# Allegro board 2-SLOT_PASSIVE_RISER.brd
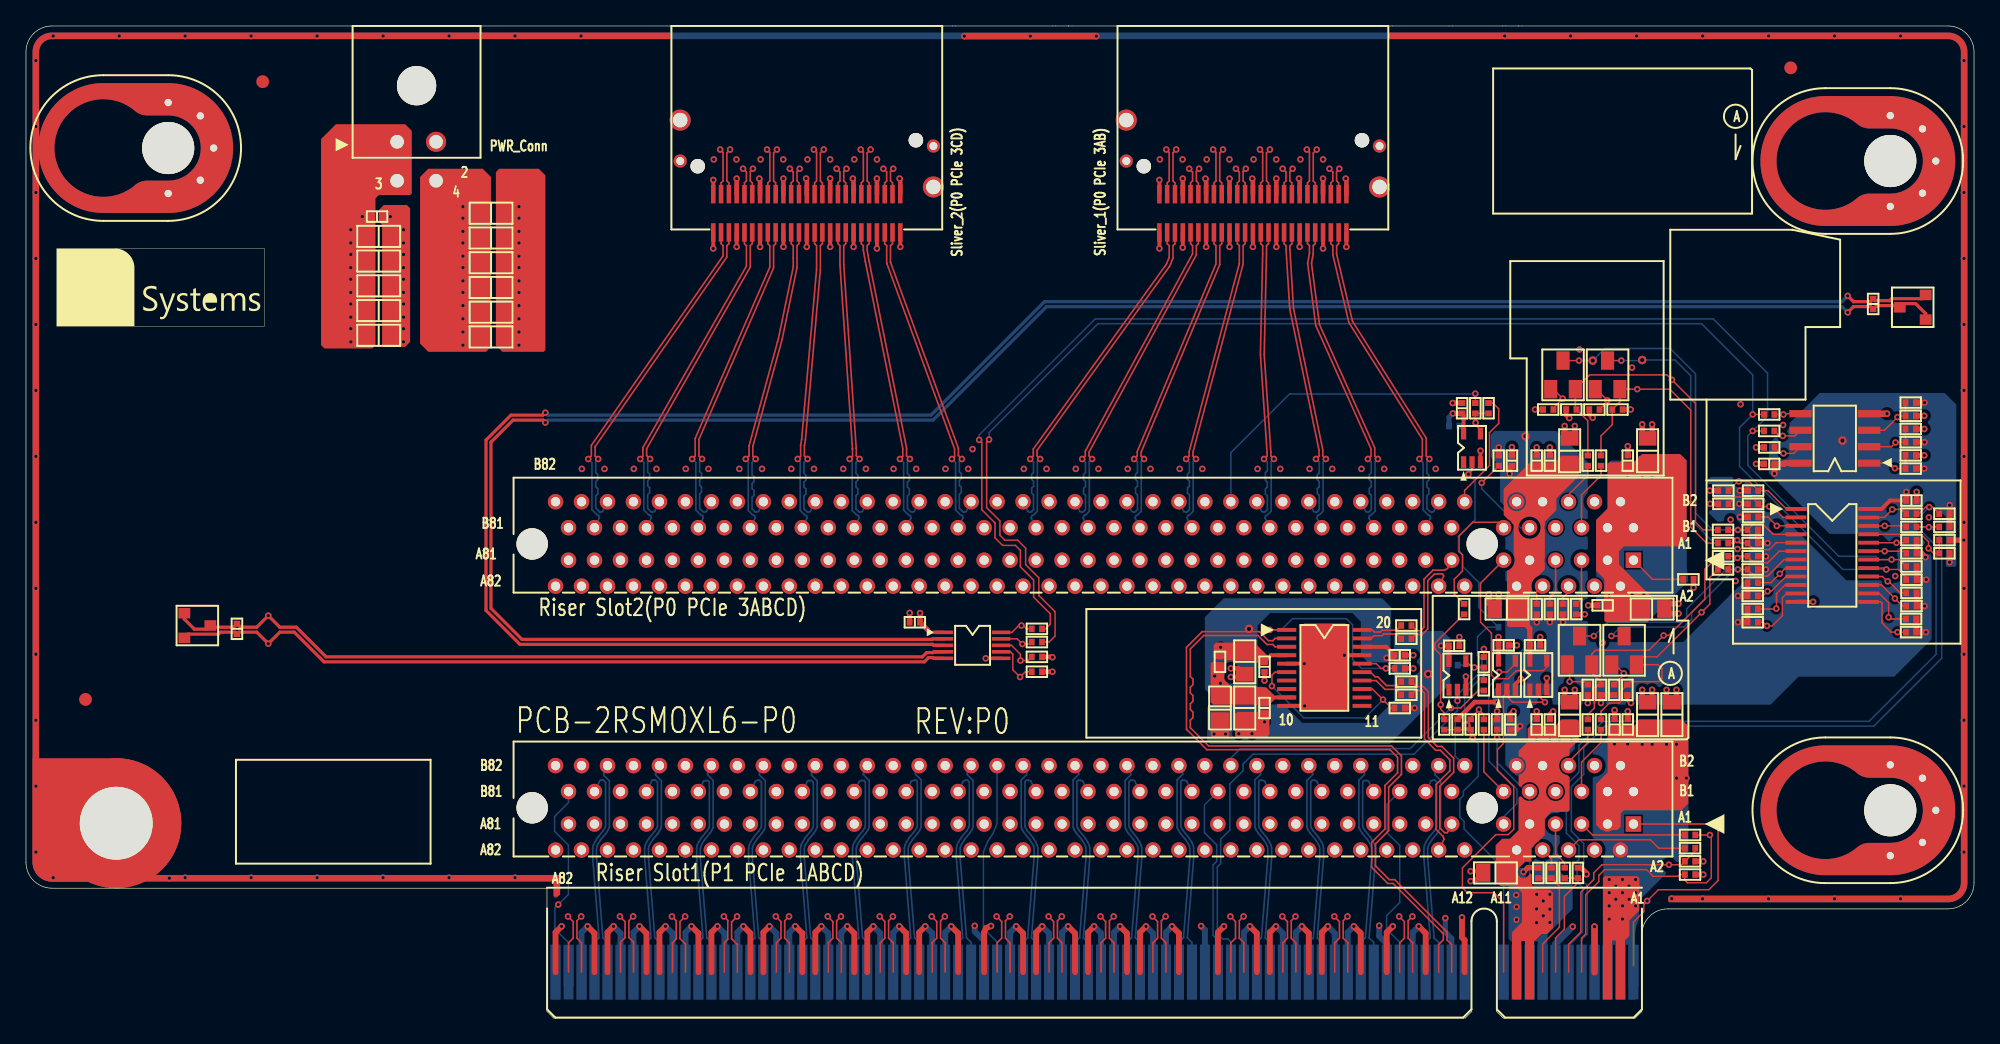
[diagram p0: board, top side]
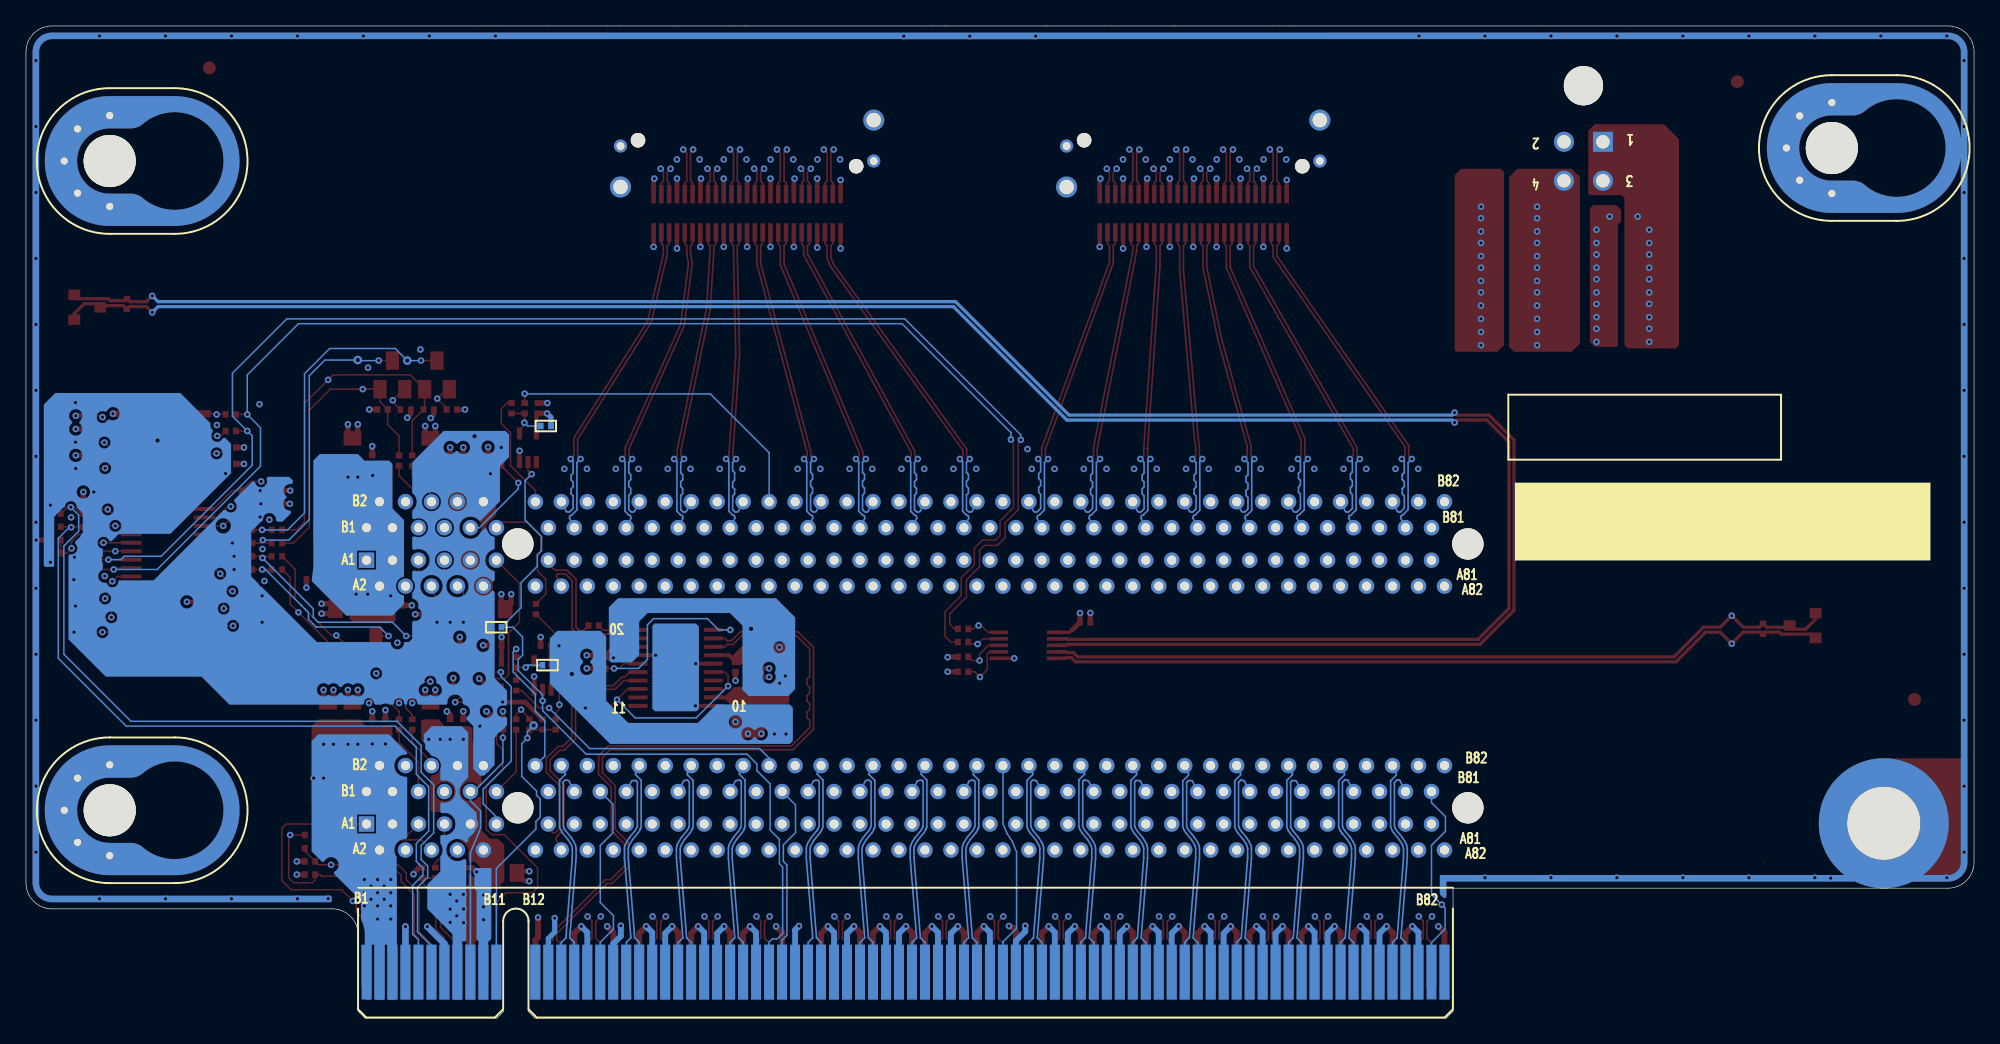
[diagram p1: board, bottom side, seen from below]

Outline 150 x 76.4 mm; copper layers: TOP, GND, IN1, IN2, GND1, BOTTOM. Coordinates in mm from the lower left corner of the outline.
Outline path: 0,74.4 arc(0.59,75.81) 2,76.4 148,76.4 arc(149.41,75.81) 150,74.4 150,10.41 arc(149.41,8.99) 148,8.41 126.42,8.41 arc(125,7.82) 124.42,6.41 124.42,0.51 123.91,0 113.74,0 113.23,0.51 113.23,7.45 arc(112.28,8.41) 111.32,7.45 111.32,0.51 110.82,0 40.62,0 40.12,0.51 40.12,10 2,10 arc(0.59,10.59) 0,12 0,74.4

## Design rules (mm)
constraint set DEFAULT: min track width 0.117
net group CLK_100M_SLOT1_R_DN: nets CLK_100M_SLOT2_DN CLK_100M_SLOT2_R_DN
net group CLK_100M_SLOT1_R_DP: nets CLK_100M_SLOT2_DP CLK_100M_SLOT2_R_DP
net group CLK_100M_SLOT2_R_DN: nets CLK_100M_SLOT1_DN CLK_100M_SLOT1_R_DN
net group CLK_100M_SLOT2_R_DP: nets CLK_100M_SLOT1_DP CLK_100M_SLOT1_R_DP
net group I2C_MB_RISER_SDA: nets I2C_MB_RISER_SDA I2C_PCA9548_SDA
net group I2C_PCA9548_SCL: nets I2C_MB_RISER_SCL I2C_PCA9548_SCL
net group I2C_EMC1413_SCL: nets I2C_BUF_CH6_SCL I2C_EMC1413_SCL I2C_FRU_SCL
net group I2C_FRU_SDA: nets I2C_BUF_CH6_SDA I2C_EMC1413_SDA I2C_FRU_SDA
net group I2C_SLOT1_SCL: nets I2C_BUF_SLOT1_SCL I2C_SLOT1_R_SCL I2C_SLOT1_SCL
net group I2C_SLOT1_SDA: nets I2C_BUF_SLOT1_SDA I2C_SLOT1_R_SDA I2C_SLOT1_SDA
net group I2C_SLOT2_SCL: nets I2C_BUF_SLOT2_SCL I2C_SLOT2_R_SCL I2C_SLOT2_SCL
net group I2C_SLOT2_SDA: nets I2C_BUF_SLOT2_SDA I2C_SLOT2_R_SDA I2C_SLOT2_SDA

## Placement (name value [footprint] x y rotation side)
C1  -  [C0805]  124.86 43.69 90 top
C2  -  [C0805]  114.03 31.5 180 top
C3  -  [C0402]  123.34 42.93 90 top
C4  -  [C0402]  117.34 42.93 90 top
C5  -  [C0402]  121.4 31.78 180 top
C6  -  [C0402]  116.32 42.93 90 top
C7  -  [C0402]  114.42 42.93 90 top
C8  -  [C0805]  124.86 23.37 90 top
C9  -  [C0805]  118.86 23.37 90 top
C10  -  [C0402]  123.34 22.61 90 top
C11  -  [C0402]  117.34 22.61 90 top
C12  -  [C0402]  122.32 22.61 90 top
C13  -  [C0402]  116.32 22.61 90 top
C14  -  [C0402]  114.29 22.61 90 top
C15  -  [C0805]  93.84 27.43 270 top
C16  -  [C0402]  95.37 27.05 270 top
C17  -  [C0805]  93.84 23.88 270 top
C18  -  [C0402]  105.78 27.94 0 top
C19  -  [C0402]  95.37 23.88 270 top
C20  -  [C0402]  145.18 39.85 0 top
C21  -  [C0402]  68.44 30.48 180 top
C22  -  [C0402]  134.23 42.67 180 top
C23  -  [C0402]  16.24 29.97 270 top
C24  -  [C0402]  142.23 54.99 90 top
C25  -  [C0402]  110.58 46.96 90 top
C26  -  [C0402]  116.19 28.7 0 top
C27  -  [C0402]  113.78 28.7 0 top
C28  -  [C0402]  109.97 28.67 0 top
C29  -  [C0402]  27.03 61.72 180 top
C30  -  [C0805]  27.16 52.58 180 top
C31  -  [C0805]  27.16 54.48 180 top
C32  -  [C0805]  125.21 31.5 0 top
C33  -  [C0805]  118.86 43.69 90 top
C34  -  [C0805]  126.73 23.37 90 top
C35  -  [C0805]  113.15 11.18 180 top
C36  -  [C0805]  35.81 60.07 0 top
C37  -  [C0805]  35.81 56.26 0 top
C38  -  [C0805]  35.81 54.36 0 top
C39  -  [C0805]  27.16 56.39 180 top
C40  -  [C0805]  35.81 61.98 0 top
C41  -  [C0805]  27.16 60.2 180 top
C42  -  [C0805]  35.81 52.45 0 top
C43  -  [C0805]  27.16 58.29 180 top
C44  -  [C0805]  35.81 58.17 0 top
J1  -  [PCIE_X16D_H11]  123.78 14.94 270 top
J2  -  [PCIE_X16D_H11]  123.78 35.26 270 top
J3  -  [GF_PCIE_X16]  112.28 7.45 180 bottom
J4  -  [SLIVER_X8_RA]  94.45 68.57 180 top
J5  -  [SLIVER_X8_RA]  60.1 68.57 180 top
J6  -  [PWR2X2D1NH_P3W3H8-9_RA]  28.57 67.48 180 top
L1  -  [B2012]  91.94 23.88 90 top
ME1  -  [ZT_LOG_6X16]  2.35 53.26 0 top
ME2  -  [LABEL_32X6_FULL]  35.36 35.23 180 bottom
ME3  -  [LABEL20X4_SST21X5]  35.86 43 180 bottom
MH1  -  [HOLE_C10D5-6B10_NPB_STANDOFF]  6.95 15 180 bottom
MH2  -  [GND_C10D4_6-5B10_OB5]  10.95 67 270 top
MH3  -  [GND_C10D4_6-5B10_OB5]  143.55 66 270 top
MH5  -  [GND_C10D4_6-5B10_OB5]  143.55 16 270 top
NOREF  -  []  61.05 66.88 0 top
NOREF#2  -  []  46.24 7.82 0 top
NOREF#3  -  []  70.24 7.82 0 top
NOREF#4  -  [unnamed#2]  18.23 72.11 0 top
NOREF#5  -  []  85.71 43.05 0 top
NOREF#6  -  []  62.8 65.41 0 top
NOREF#7  -  []  47.68 43.05 0 top
NOREF#8  -  []  103.71 43.05 0 top
NOREF#9  -  []  67.68 43.05 0 top
NOREF#10  -  []  95.4 66.88 0 top
NOREF#11  -  []  53.83 66.88 0 top
NOREF#12  -  []  42.24 7.82 0 top
NOREF#13  -  []  93.24 7.82 0 top
NOREF#14  -  [unnamed#2]  4.59 24.54 0 top
NOREF#15  -  []  95.71 43.05 0 top
NOREF#16  -  []  99.71 43.05 0 top
NOREF#17  -  []  63.8 43.05 0 top
NOREF#18  -  []  66.24 7.82 0 top
NOREF#19  -  []  58.24 7.82 0 top
NOREF#20  -  []  93.55 65.41 0 top
NOREF#21  -  []  81.71 43.05 0 top
NOREF#22  -  []  14.59 -76.5 0 top
NOREF#23  -  []  91.79 66.88 0 top
NOREF#24  -  []  88.18 66.88 0 top
NOREF#25  -  []  55.6 65.41 0 top
NOREF#26  -  []  64.65 66.88 0 top
NOREF#27  -  []  101.24 7.82 0 top
NOREF#28  -  []  62.24 7.82 0 top
NOREF#29  -  []  54.24 7.82 0 top
NOREF#30  -  []  99 66.88 0 top
NOREF#31  -  []  59.2 65.41 0 top
NOREF#32  -  []  97.15 65.41 0 top
NOREF#33  -  []  55.8 43.05 0 top
NOREF#34  -  []  87.24 7.82 0 top
NOREF#35  -  []  66.4 65.41 0 top
NOREF#36  -  []  75.24 7.82 0 top
NOREF#37  -  []  77.71 43.05 0 top
NOREF#38  -  []  50.24 7.82 0 top
NOREF#39  -  []  43.68 43.05 0 top
NOREF#40  -  []  57.44 66.88 0 top
NOREF#41  -  [unnamed#2]  135.88 73.18 0 top
NOREF#42  -  []  89.71 43.05 0 top
NOREF#43  -  []  51.68 43.05 0 top
NOREF#44  -  []  107.68 43.05 0 top
NOREF#45  -  []  83.24 7.82 0 top
NOREF#46  -  []  89.95 65.41 0 top
NOREF#47  -  []  71.68 43.05 0 top
NOREF#48  -  []  59.8 43.05 0 top
NOREF#49  -  []  106.24 7.82 0 top
NOREF#50  -  []  97.24 7.82 0 top
NOREF#51  -  [unnamed#2]  16.17 11.89 0 top
NOREF#52  -  []  100.75 65.41 0 top
NOREF#53  -  []  79.24 7.82 0 top
Q1  -  [SOT23_GDS]  118.35 49.53 90 top
Q2  -  [SOT23_GDS]  119.62 28.32 90 top
Q3  -  [SOT23_GDS]  121.78 49.53 90 top
Q4  -  [SOT23_GDS]  123.05 28.32 90 top
Q5  -  [SOT23]  13.2 30.23 0 top
Q6  -  [SOT23]  145.28 54.74 180 top
R1  -  [R0402]  121.27 42.93 270 top
R2  -  [R0402]  120.26 42.93 270 top
R3  -  [R0402]  110.73 31.5 90 top
R4  -  [R0402]  128 33.78 0 top
R5  -  [R0402]  128.13 12.06 180 top
R6  -  [R0402]  119.5 11.18 270 top
R7  -  [R0402]  116.45 11.18 270 top
R8  -  [R0402]  128.13 11.05 180 top
R9  -  [R0402]  121.27 22.61 270 top
R10  -  [R0402]  120.26 22.61 270 top
R11  -  [R0402]  112.26 22.61 270 top
R12  -  [R0402]  130.7 40.62 180 top
R13  -  [R0402]  132.99 39.6 0 top
R14  -  [R0402]  130.7 39.6 180 top
R15  -  [R0402]  91.94 27.43 90 top
R16  -  [R0402]  147.72 36.81 0 top
R17  -  [R0402]  145.18 38.84 180 top
R18  -  [R0402]  105.78 26.92 180 top
R19  -  [R0402]  105.78 23.88 180 top
R20  -  [R0402]  132.96 37.59 180 top
R21  -  [R0402]  132.96 36.58 180 top
R22  -  [R0402]  132.96 35.56 180 top
R23  -  [R0402]  132.96 34.54 180 top
R24  -  [R0402]  132.96 33.53 0 top
R25  -  [R0402]  132.96 32.51 0 top
R26  -  [R0402]  147.72 38.84 180 top
R27  -  [R0402]  147.72 37.82 180 top
R28  -  [R0402]  106.29 30.23 0 top
R29  -  [R0402]  106.29 29.21 0 top
R30  -  [R0402]  106.29 25.91 0 top
R31  -  [R0402]  106.29 24.89 0 top
R32  -  [R0402]  117.21 46.86 0 top
R33  -  [R0402]  120.26 25.27 90 top
R34  -  [R0402]  120.77 46.86 0 top
R35  -  [R0402]  122.29 25.27 90 top
R36  -  [R0402]  118.99 46.86 0 top
R37  -  [R0402]  121.27 25.27 90 top
R38  -  [R0402]  122.54 46.86 180 top
R39  -  [R0402]  123.31 25.27 90 top
R40  -  [R0402]  134.23 46.48 0 top
R41  -  [R0402]  77.84 28.96 180 top
R42  -  [R0402]  134.23 43.94 180 top
R43  -  [R0402]  145.12 43.33 0 top
R44  -  [R0402]  145.12 44.35 180 top
R45  -  [R0402]  145.12 45.36 0 top
R46  -  [R0402]  145.12 47.39 180 top
R47  -  [R0402]  145.12 46.38 0 top
R48  -  [R0402]  109.21 22.61 270 top
R49  -  [R0402]  111.24 22.61 270 top
R50  -  [R0402]  113.27 22.61 270 top
R51  -  [R0402]  128.13 14.1 0 top
R52  -  [R0402]  128.13 13.08 0 top
R53  -  [R0402]  118.48 11.18 270 top
R54  -  [R0402]  117.46 11.18 270 top
R55  -  [R0402]  132.99 40.62 0 top
R56  -  [R0402]  147.72 35.79 180 top
R57  -  [R0402]  145.18 37.82 180 top
R58  -  [R0402]  134.23 45.21 0 top
R59  -  [R0402]  77.84 29.97 180 top
R60  -  [R0402]  145.12 42.31 180 top
R61  -  [R0402]  110.22 22.61 270 top
R62  -  [R0402]  132.99 38.58 0 top
R63  -  [R0402]  132.96 31.5 0 top
R64  -  [R0402]  132.96 30.48 0 top
R65  -  [R0402]  145.15 29.72 180 top
R66  -  [R0402]  145.15 30.73 180 top
R67  -  [R0402]  145.18 31.73 180 top
R68  -  [R0402]  145.18 32.74 180 top
R69  -  [R0402]  145.18 33.76 180 top
R70  -  [R0402]  145.18 34.77 180 top
R71  -  [R0402]  145.18 35.79 180 top
R72  -  [R0402]  145.18 36.81 180 top
R73  -  [R0402]  112.61 46.96 90 top
R74  -  [R0402]  111.6 46.96 90 top
R75  -  [R0402]  112.25 27.4 90 top
R76  -  [R0402]  112.25 25.62 270 top
R77  -  [R0402]  113.4 42.93 270 top
R78  -  [R0402]  118.35 31.5 90 top
R79  -  [R0402]  117.34 31.5 90 top
R80  -  [R0402]  116.32 31.5 90 top
R81  -  [R0402]  119.37 31.5 90 top
R82  -  [R0402]  130.67 36.58 180 top
R83  -  [R0402]  130.67 34.54 180 top
R84  -  [R0402]  130.67 37.59 180 top
R85  -  [R0402]  130.67 35.56 180 top
R86  -  [R0402]  77.84 27.81 180 top
R87  -  [R0402]  77.84 26.67 180 top
R88  -  [R0402]  113.78 30.1 180 bottom
R89  -  [R0402]  109.97 45.59 0 bottom
R90  -  [R0402]  109.84 27.18 0 bottom
U1  -  [TSSOP24_P0-65W5-6H1-2]  139.08 35.63 0 top
U2  -  [MSOP10_P0-5W4-4_3X3]  72.89 28.7 0 top
U3  -  [SOIC8]  139.28 44.64 180 top
U4  -  [SC70-5XB]  116.45 26.42 90 top
U5  -  [SC70-5XB]  111.34 43.91 90 top
U6  -  [SC70-5XB]  114.03 26.42 90 top
U7  -  [SC70-5XB]  110.22 26.38 90 top
U8  -  [TSSOP20_P0-65W5-8H1-2]  99.97 26.96 0 top

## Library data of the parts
C1 C2 C8 C9 C15 C17 = CAP: part number: CAP_0805-10UF,CAP-85E00010-D0,X6S,10%,16V
C3-C7 C10-C14 C16 C18-C22 C25-C29 = CAP: part number: CAP_0402-0.1UF,CAP-42E000D1-D0,X7R,10%,16V
C23 C24 = CAP: part number: CAP_0402-2200PF,CAP-42GD0022-D0,X7R,10%,50V
C30-C44 = CAP: part number: CAP_0805-22UF,CAP-85E00022-E0,X6S,20%,16V
J1 J2 = PCIE_X16: part number: PCIE_X16_-2EG08213-9ADM-JF,COB-PCE164DV-03,IO,,
J3 = GF_PCIE_X16: part number: GF_PCIE_X16_-GF_PCIE_X16,,,,
J4 J5 = SLIVER_X8_50P: part number: SLIVER_X8_50P_-2292055-1,COS-SLV050SR-00,IO,,
J6 = PWR2X2: part number: PWR2X2_-1NH_PWR2X2,COP-004D0003-01,IO,,,
L1 = BEAD: part number: BEAD_-600,BED-06002012-00,IC,25%,,
ME1 = DUMMY_SYMBOL_NO_PIN: part number: DUMMY_SYMBOL_NO_PIN_-ZT_LOG_6X16,MEDUMMY3,EMPTY,,
ME2 = DUMMY_SYMBOL_NO_PIN: part number: DUMMY_SYMBOL_NO_PIN_-LABEL_32X6_FULL,MEDUMMY7,EMPTY,,
ME3 = DUMMY_SYMBOL_NO_PIN: part number: DUMMY_SYMBOL_NO_PIN_-LABEL20X4_SST21X5,MEDUMMY5,EMPTY,,
MH1 = STANDOFF: part number: STANDOFF_-HOLE_C10D5-6B10_NPB_STANDOFF,TSW-AM3L5P1P-00,IO,,
MH2 MH3 MH5 = SCREW_NP_5VIA: part number: SCREW_NP_5VIA_-C10D4XC10D6.5_5V,TEMP_C10D4XC10D6.5_L5,EMPTY,,
Q1 Q3 = 2N7002: part number: 2N7002_-2N7002,MOS-002N7002-00,EMPTY,,,; signal model: 2N7002_-2N7002_MOS-002N7002-00A
Q2 Q4 = 2N7002: part number: 2N7002_-2N7002,MOS-002N7002-00,IC,,,; signal model: 2N7002_-2N7002_MOS-002N7002-00A
Q5 Q6 = NPN: part number: NPN_-MMBT3904LT1G,BJT-MMBT3904-00,IC,,,
R1 R2 R9 R10 R40 R41 R58 R59 R82 R84 = RES: part number: RES_0402-0,RES-42000000-C0,IC,5%,1A; signal model: R0402
R3 R11 R15 R48 R49 R51-R54 R74 R76 = RES: part number: RES_0402-0,RES-42000000-C0,IC,5%,1A
R4 R89 R90 = RES: part number: RES_0402-10K,RES-4200010K-B0,IC,1%,1/16W
R5-R8 R55 R56 R60 R61 R77-R81 = RES: part number: RES_0402-4.7K,RES-42004D7K-B0,EMPTY,1%,1/16W
R12 R16 R18 R32-R35 R42 R43 = RES: part number: RES_0402-100,RES-42000100-B0,IC,1%,1/16W
R13 R19 R24 R25 R44 R46 R62-R68 R71 R72 R86 R87 = RES: part number: RES_0402-4.7K,RES-42004D7K-B0,IC,1%,1/16W
R14 R45 R47 = RES: part number: RES_0402-100,RES-42000100-B0,EMPTY,1%,1/16W
R17 R57 = RES: part number: RES_0402-22,RES-42000022-B0,IC,1%,1/16W; signal model: R0402
R20-R23 R37 R39 R69 R70 = RES: part number: RES_0402-4.7K,RES-42004D7K-B0,IC,1%,1/16W; signal model: R0402
R26 R27 R36 R38 = RES: part number: RES_0402-4.7K,RES-42004D7K-B0,EMPTY,1%,1/16W; signal model: R0402
R28-R31 = RES: part number: RES_0402-27.4,RES-420027D4-B0,IC,1%,1/16W; signal model: R0402
R50 R88 = RES: part number: RES_0402-10K,RES-4200010K-B0,EMPTY,1%,1/16W
R73 R75 = RES: part number: RES_0402-0,RES-42000000-C0,EMPTY,5%,1A
R83 R85 = RES: part number: RES_0402-0,RES-42000000-C0,EMPTY,5%,1A; signal model: R0402
U1 = PCA9548: part number: PCA9548_-PCA9548APW,ICC-PCA9548A-00,IC,,
U2 = EMC1413AAIZLTR: part number: EMC1413AAIZLTR_-EMC1413-A-AIZL-TR,ICC-EMC1413A-00,IC,,
U3 = AT24C64D: part number: AT24C64D_-AT24C64D-SSHM-T,ICM-AT24C64D-00,IC,,
U4 U6 = SN74LVC1G17: part number: SN74LVC1G17_-SN74LVC1G17DCKR,ICC-LVC1G17D-00,IC,,,
U5 U7 = SN74LVC1G07: part number: SN74LVC1G07_-SN74LVC1G07DCKR,ICC-LVC1G07D-00,IC,,,
U8 = 9DBL411B: part number: 9DBL411B_-9DBL411BGILFT,ICC-9DBL411B-00,IC,,

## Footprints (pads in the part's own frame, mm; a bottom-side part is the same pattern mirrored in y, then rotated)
B2012
  rect 1.118x1.372 smd: 1(-0.95,0) 2(0.95,0)
C0402
  rect 0.457x0.508 smd: 1(-0.4,0) 2(0.4,0)
C0805
  rect 1.118x1.372 smd: 1(-0.95,0) 2(0.95,0)
GF_PCIE_X16
  rect 0.762x3.2 smd: A1(-11.5,-3.42) B81(70.5,-3.42)
  rect 0.762x4.216 smd: A2(-10.5,-3.92) A3(-9.5,-3.92) A4(-8.5,-3.92) A5(-7.5,-3.92) A6(-6.5,-3.92) A7(-5.5,-3.92) A8(-4.5,-3.92) A9(-3.5,-3.92) A10(-2.5,-3.92) A11(-1.5,-3.92) A12(1.5,-3.92) A13(2.5,-3.92) A14(3.5,-3.92) A15(4.5,-3.92) A16(5.5,-3.92) A17(6.5,-3.92) A18(7.5,-3.92) A19(8.5,-3.92) A20(9.5,-3.92) A21(10.5,-3.92) A22(11.5,-3.92) A23(12.5,-3.92) A24(13.5,-3.92) A25(14.5,-3.92) A26(15.5,-3.92) A27(16.5,-3.92) A28(17.5,-3.92) A29(18.5,-3.92) A30(19.5,-3.92) A31(20.5,-3.92) A32(21.5,-3.92) A33(22.5,-3.92) A34(23.5,-3.92) A35(24.5,-3.92) A36(25.5,-3.92) A37(26.5,-3.92) A38(27.5,-3.92) A39(28.5,-3.92) A40(29.5,-3.92) A41(30.5,-3.92) A42(31.5,-3.92) A43(32.5,-3.92) A44(33.5,-3.92) A45(34.5,-3.92) A46(35.5,-3.92) A47(36.5,-3.92) A48(37.5,-3.92) A49(38.5,-3.92) A50(39.5,-3.92) A51(40.5,-3.92) A52(41.5,-3.92) A53(42.5,-3.92) A54(43.5,-3.92) A55(44.5,-3.92) A56(45.5,-3.92) A57(46.5,-3.92) A58(47.5,-3.92) A59(48.5,-3.92) A60(49.5,-3.92) A61(50.5,-3.92) A62(51.5,-3.92) A63(52.5,-3.92) A64(53.5,-3.92) A65(54.5,-3.92) A66(55.5,-3.92) A67(56.5,-3.92) A68(57.5,-3.92) A69(58.5,-3.92) A70(59.5,-3.92) A71(60.5,-3.92) A72(61.5,-3.92) A73(62.5,-3.92) A74(63.5,-3.92) A75(64.5,-3.92) A76(65.5,-3.92) A77(66.5,-3.92) A78(67.5,-3.92) A79(68.5,-3.92) A80(69.5,-3.92) A81(70.5,-3.92) A82(71.5,-3.92) B1(-11.5,-3.92) B2(-10.5,-3.92) B3(-9.5,-3.92) B4(-8.5,-3.92) B5(-7.5,-3.92) B6(-6.5,-3.92) B7(-5.5,-3.92) B8(-4.5,-3.92) B9(-3.5,-3.92) B10(-2.5,-3.92) B11(-1.5,-3.92) B12(1.5,-3.92) B13(2.5,-3.92) B14(3.5,-3.92) B15(4.5,-3.92) B16(5.5,-3.92) B17(6.5,-3.92) B18(7.5,-3.92) B19(8.5,-3.92) B20(9.5,-3.92) B21(10.5,-3.92) B22(11.5,-3.92) B23(12.5,-3.92) B24(13.5,-3.92) B25(14.5,-3.92) B26(15.5,-3.92) B27(16.5,-3.92) B28(17.5,-3.92) B29(18.5,-3.92) B30(19.5,-3.92) B31(20.5,-3.92) B32(21.5,-3.92) B33(22.5,-3.92) B34(23.5,-3.92) B35(24.5,-3.92) B36(25.5,-3.92) B37(26.5,-3.92) B38(27.5,-3.92) B39(28.5,-3.92) B40(29.5,-3.92) B41(30.5,-3.92) B42(31.5,-3.92) B43(32.5,-3.92) B44(33.5,-3.92) B45(34.5,-3.92) B46(35.5,-3.92) B47(36.5,-3.92) B48(37.5,-3.92) B49(38.5,-3.92) B50(39.5,-3.92) B51(40.5,-3.92) B52(41.5,-3.92) B53(42.5,-3.92) B54(43.5,-3.92) B55(44.5,-3.92) B56(45.5,-3.92) B57(46.5,-3.92) B58(47.5,-3.92) B59(48.5,-3.92) B60(49.5,-3.92) B61(50.5,-3.92) B62(51.5,-3.92) B63(52.5,-3.92) B64(53.5,-3.92) B65(54.5,-3.92) B66(55.5,-3.92) B67(56.5,-3.92) B68(57.5,-3.92) B69(58.5,-3.92) B70(59.5,-3.92) B71(60.5,-3.92) B72(61.5,-3.92) B73(62.5,-3.92) B74(63.5,-3.92) B75(64.5,-3.92) B76(65.5,-3.92) B77(66.5,-3.92) B78(67.5,-3.92) B79(68.5,-3.92) B80(69.5,-3.92) B82(71.5,-3.92)
GND_C10D4_6-5B10_OB5
  round 4.013 hole 4.013 unplated: (0,0)
  round 0.762 hole 0.559: 2(-3.5,0) 3(-2.475,2.475) 4(0,3.5) 5(2.475,2.475) 6(3.5,0)
HOLE_C10D5-6B10_NPB_STANDOFF
  round 10.008 hole 5.613: 1(0,0)
MSOP10_P0-5W4-4_3X3
  rect 1.422x0.279 smd: 1(-2.2,1) 2(-2.2,0.5) 3(-2.2,0) 4(-2.2,-0.5) 5(-2.2,-1) 6(2.2,-1) 7(2.2,-0.5) 8(2.2,0) 9(2.2,0.5) 10(2.2,1)
PCIE_X16D_H11
  round 2.413 hole 2.413 unplated: (-1.25,-11.65) (-1.25,-84.8)
  rect 1.194x1.194 hole 0.711: A1(0,0)
  round 1.194 hole 0.711: A2(2,-1) A3(0,-2) A4(2,-3) A5(0,-4) A6(2,-5) A7(0,-6) A8(2,-7) A9(0,-8) A10(2,-9) A11(0,-10) A12(2,-13) A13(0,-14) A14(2,-15) A15(0,-16) A16(2,-17) A17(0,-18) A18(2,-19) A19(0,-20) A20(2,-21) A21(0,-22) A22(2,-23) A23(0,-24) A24(2,-25) A25(0,-26) A26(2,-27) A27(0,-28) A28(2,-29) A29(0,-30) A30(2,-31) A31(0,-32) A32(2,-33) A33(0,-34) A34(2,-35) A35(0,-36) A36(2,-37) A37(0,-38) A38(2,-39) A39(0,-40) A40(2,-41) A41(0,-42) A42(2,-43) A43(0,-44) A44(2,-45) A45(0,-46) A46(2,-47) A47(0,-48) A48(2,-49) A49(0,-50) A50(2,-51) A51(0,-52) A52(2,-53) A53(0,-54) A54(2,-55) A55(0,-56) A56(2,-57) A57(0,-58) A58(2,-59) A59(0,-60) A60(2,-61) A61(0,-62) A62(2,-63) A63(0,-64) A64(2,-65) A65(0,-66) A66(2,-67) A67(0,-68) A68(2,-69) A69(0,-70) A70(2,-71) A71(0,-72) A72(2,-73) A73(0,-74) A74(2,-75) A75(0,-76) A76(2,-77) A77(0,-78) A78(2,-79) A79(0,-80) A80(2,-81) A81(0,-82) A82(2,-83) B1(-2.5,0) B2(-4.5,-1) B3(-2.5,-2) B4(-4.5,-3) B5(-2.5,-4) B6(-4.5,-5) B7(-2.5,-6) B8(-4.5,-7) B9(-2.5,-8) B10(-4.5,-9) B11(-2.5,-10) B12(-4.5,-13) B13(-2.5,-14) B14(-4.5,-15) B15(-2.5,-16) B16(-4.5,-17) B17(-2.5,-18) B18(-4.5,-19) B19(-2.5,-20) B20(-4.5,-21) B21(-2.5,-22) B22(-4.5,-23) B23(-2.5,-24) B24(-4.5,-25) B25(-2.5,-26) B26(-4.5,-27) B27(-2.5,-28) B28(-4.5,-29) B29(-2.5,-30) B30(-4.5,-31) B31(-2.5,-32) B32(-4.5,-33) B33(-2.5,-34) B34(-4.5,-35) B35(-2.5,-36) B36(-4.5,-37) B37(-2.5,-38) B38(-4.5,-39) B39(-2.5,-40) B40(-4.5,-41) B41(-2.5,-42) B42(-4.5,-43) B43(-2.5,-44) B44(-4.5,-45) B45(-2.5,-46) B46(-4.5,-47) B47(-2.5,-48) B48(-4.5,-49) B49(-2.5,-50) B50(-4.5,-51) B51(-2.5,-52) B52(-4.5,-53) B53(-2.5,-54) B54(-4.5,-55) B55(-2.5,-56) B56(-4.5,-57) B57(-2.5,-58) B58(-4.5,-59) B59(-2.5,-60) B60(-4.5,-61) B61(-2.5,-62) B62(-4.5,-63) B63(-2.5,-64) B64(-4.5,-65) B65(-2.5,-66) B66(-4.5,-67) B67(-2.5,-68) B68(-4.5,-69) B69(-2.5,-70) B70(-4.5,-71) B71(-2.5,-72) B72(-4.5,-73) B73(-2.5,-74) B74(-4.5,-75) B75(-2.5,-76) B76(-4.5,-77) B77(-2.5,-78) B78(-4.5,-79) B79(-2.5,-80) B80(-4.5,-81) B81(-2.5,-82) B82(-4.5,-83)
PWR2X2D1NH_P3W3H8-9_RA
  round 3.023 hole 3.023 unplated: (-1.5,-4.32)
  rect 1.549x1.549 hole 1.041: 1(0,0)
  round 1.549 hole 1.041: 2(-3,0) 3(0,3) 4(-3,3)
R0402
  rect 0.457x0.508 smd: 1(-0.4,0) 2(0.4,0)
SC70-5XB
  rect 0.914x0.406 smd: 1(-1.1,0.65) 2(-1.1,0) 3(-1.1,-0.65) 4(1.1,-0.65) 5(1.1,0.65)
SLIVER_X8_RA
  round 1.118 hole 1.118 unplated: (-8.425,0.965) (8.375,2.965)
  rect 0.356x1.422 smd: 1(-7.225,5.115) 2(-6.625,5.115) 3(-6.025,5.115) 4(-5.425,5.115) 5(-4.825,5.115) 6(-4.225,5.115) 7(-3.625,5.115) 8(-3.025,5.115) 9(-2.425,5.115) 10(-1.825,5.115) 11(-1.225,5.115) 12(-0.625,5.115) 13(-0.025,5.115) 14(0.575,5.115) 15(1.175,5.115) 16(1.775,5.115) 17(2.375,5.115) 18(2.975,5.115) 19(3.575,5.115) 20(4.175,5.115) 21(4.775,5.115) 22(5.375,5.115) 23(5.975,5.115) 24(6.575,5.115) 25(7.175,5.115) 26(7.175,8.065) 27(6.575,8.065) 28(5.975,8.065) 29(5.375,8.065) 30(4.775,8.065) 31(4.175,8.065) 32(3.575,8.065) 33(2.975,8.065) 34(2.375,8.065) 35(1.775,8.065) 36(1.175,8.065) 37(0.575,8.065) 38(-0.025,8.065) 39(-0.625,8.065) 40(-1.225,8.065) 41(-1.825,8.065) 42(-2.425,8.065) 43(-3.025,8.065) 44(-3.625,8.065) 45(-4.225,8.065) 46(-4.825,8.065) 47(-5.425,8.065) 48(-6.025,8.065) 49(-6.625,8.065) 50(-7.225,8.065)
  round 1.626 hole 1.118: G1(-9.775,4.565) G4(9.725,-0.585)
  round 1.016 hole 0.61: G2(-9.775,1.411) G3(9.725,2.565)
SOIC8
  rect 1.727x0.559 smd: 1(-2.642,1.905) 2(-2.642,0.635) 3(-2.642,-0.635) 4(-2.642,-1.905) 5(2.642,-1.905) 6(2.642,-0.635) 7(2.642,0.635) 8(2.642,1.905)
SOT23
  rect 0.914x0.813 smd: 1(-1,0.95) 2(-1,-0.95) 3(1,0)
SOT23_GDS
  rect 1.422x1.016 smd: D(1.1,0) G(-1.1,0.95) S(-1.1,-0.95)
TSSOP20_P0-65W5-8H1-2
  rect 1.473x0.305 smd: 1(-2.9,2.925) 2(-2.9,2.275) 3(-2.9,1.625) 4(-2.9,0.975) 5(-2.9,0.325) 6(-2.9,-0.325) 7(-2.9,-0.975) 8(-2.9,-1.625) 9(-2.9,-2.275) 10(-2.9,-2.925) 11(2.9,-2.925) 12(2.9,-2.275) 13(2.9,-1.625) 14(2.9,-0.975) 15(2.9,-0.325) 16(2.9,0.325) 17(2.9,0.975) 18(2.9,1.625) 19(2.9,2.275) 20(2.9,2.925)
TSSOP24_P0-65W5-6H1-2
  rect 1.6x0.305 smd: 1(-2.8,3.575) 2(-2.8,2.925) 3(-2.8,2.275) 4(-2.8,1.625) 5(-2.8,0.975) 6(-2.8,0.325) 7(-2.8,-0.325) 8(-2.8,-0.975) 9(-2.8,-1.625) 10(-2.8,-2.275) 11(-2.8,-2.925) 12(-2.8,-3.575) 13(2.8,-3.575) 14(2.8,-2.925) 15(2.8,-2.275) 16(2.8,-1.625) 17(2.8,-0.975) 18(2.8,-0.325) 19(2.8,0.325) 20(2.8,0.975) 21(2.8,1.625) 22(2.8,2.275) 23(2.8,2.925) 24(2.8,3.575)
unnamed#2
  round 0.991 smd: 1(0,0)

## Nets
GND: C1.2(B) C2.2(B) C3.2(B) C4.2(B) C5.2(B) C6.2(B) C7.2(B) C8.2(B) C9.2(B) C10.2(B) C11.2(B) C12.2(B) C13.2(B) C14.2(B) C15.2(B) C16.2(B) C17.2(B) C18.2(B) C19.2(B) C20.2(B) C21.2(B) C22.2(B) C25.2(B) C26.2(B) C27.2(B) C28.2(B) C29.2(B) C30.2(B) C31.2(B) C32.2(B) C33.2(B) C34.2(B) C35.2(B) C36.2(B) C37.2(B) C38.2(B) C39.2(B) C40.2(B) C41.2(B) C42.2(B) C43.2(B) C44.2(B) J1.A4 J1.A12 J1.A15 J1.A18 J1.A20 J1.A23 J1.A24 J1.A27 J1.A28 J1.A31 J1.A34 J1.A37 J1.A38 J1.A41 J1.A42 J1.A45 J1.A46 J1.A49 J1.A51 J1.A54 J1.A55 J1.A58 J1.A59 J1.A62 J1.A63 J1.A66 J1.A67 J1.A70 J1.A71 J1.A74 J1.A75 J1.A78 J1.A79 J1.A82 J1.B4 J1.B7 J1.B13 J1.B16 J1.B18 J1.B21 J1.B22 J1.B25 J1.B26 J1.B29 J1.B32 J1.B35 J1.B36 J1.B39 J1.B40 J1.B43 J1.B44 J1.B47 J1.B49 J1.B52 J1.B53 J1.B56 J1.B57 J1.B60 J1.B61 J1.B64 J1.B65 J1.B68 J1.B69 J1.B72 J1.B73 J1.B76 J1.B77 J1.B80 J2.A4 J2.A12 J2.A15 J2.A18 J2.A20 J2.A23 J2.A24 J2.A27 J2.A28 J2.A31 J2.A34 J2.A37 J2.A38 J2.A41 J2.A42 J2.A45 J2.A46 J2.A49 J2.A51 J2.A54 J2.A55 J2.A58 J2.A59 J2.A62 J2.A63 J2.A66 J2.A67 J2.A70 J2.A71 J2.A74 J2.A75 J2.A78 J2.A79 J2.A82 J2.B4 J2.B7 J2.B13 J2.B16 J2.B18 J2.B21 J2.B22 J2.B25 J2.B26 J2.B29 J2.B32 J2.B35 J2.B36 J2.B39 J2.B40 J2.B43 J2.B44 J2.B47 J2.B49 J2.B52 J2.B53 J2.B56 J2.B57 J2.B60 J2.B61 J2.B64 J2.B65 J2.B68 J2.B69 J2.B72 J2.B73 J2.B76 J2.B77 J2.B80 J3.A4 J3.A12 J3.A15 J3.A18 J3.A20 J3.A23 J3.A24 J3.A27 J3.A28 J3.A31 J3.A34 J3.A37 J3.A38 J3.A41 J3.A42 J3.A45 J3.A46 J3.A49 J3.A51 J3.A54 J3.A55 J3.A58 J3.A59 J3.A62 J3.A63 J3.A66 J3.A67 J3.A70 J3.A71 J3.A74 J3.A75 J3.A78 J3.A79 J3.A82 J3.B4 J3.B7 J3.B13 J3.B16 J3.B18 J3.B21 J3.B22 J3.B25 J3.B26 J3.B29 J3.B32 J3.B35 J3.B36 J3.B39 J3.B40 J3.B43 J3.B44 J3.B47 J3.B49 J3.B52 J3.B53 J3.B56 J3.B57 J3.B60 J3.B61 J3.B64 J3.B65 J3.B68 J3.B69 J3.B72 J3.B73 J3.B76 J3.B77 J3.B80 J4.1 J4.4 J4.7 J4.10 J4.13 J4.16 J4.19 J4.22 J4.25 J4.26 J4.29 J4.32 J4.35 J4.38 J4.41 J4.44 J4.47 J4.50 J4.G1 J4.G2 J4.G3 J4.G4 J5.1 J5.4 J5.7 J5.10 J5.13 J5.16 J5.19 J5.22 J5.25 J5.26 J5.29 J5.32 J5.35 J5.38 J5.41 J5.44 J5.47 J5.50 J5.G1 J5.G2 J5.G3 J5.G4 J6.1 J6.3 MH1.1 MH2.2 MH2.3 MH2.4 MH2.5 MH2.6 MH3.2 MH3.3 MH3.4 MH3.5 MH3.6 MH5.2 MH5.3 MH5.4 MH5.5 MH5.6 R4.2(B) R8.1 R12.2(B) R14.2(B) R16.2(B) R18.1 R42.2(B) R43.2(B) R45.2(B) R47.2(B) R81.1 U1.12 U2.6 U3.4 U4.3 U5.3 U6.3 U7.3 U8.5 U8.10 U8.17
P3V3_CLK_BUF_VDDA: C15.1 C16.1 R15.2(B) U8.4
P3V3_CLK_BUF_VDDIO: C17.1 C18.1 C19.1 L1.2 R15.1 U8.9 U8.18(VDDIO2)
P3V3_SLOT1: C9.1 C11.1 C13.1 C27.1 C28.1 C35.1 J1.A9 J1.A10 J1.B8 J3.A9 J3.A10 J3.B8 L1.1 R19.1 R33.1 R35.1 R37.1 R39.1 R50.1 R90.1 U6.5 U7.5
P3V3_SLOT2: C2.1 C4.1 C6.1 C25.1 C26.1 C33.1 C36.1 C37.1 C38.1 C40.1 C42.1 C44.1 J2.A9 J2.A10 J2.B8 J6.4 R32.1 R34.1 R36.1 R38.1 R89.1 U4.5 U5.5
P3V3_STBY: C7.1 C14.1 C20.1 C21.1 C22.1 J1.B10 J2.B10 J3.B10 R5.1 R6.1 R7.1 R13.1 R20.1 R21.1 R22.1 R23.1 R24.1 R25.1 R26.1 R27.1 R44.1 R46.1 R55.1 R56.1 R60.1 R61.1 R62.1 R63.1 R64.1 R65.1 R66.1 R67.1 R68.1 R69.1 R70.1 R71.1 R72.1 R77.1 R78.1 R79.1 R80.1 R86.1 R87.1 R88.1 U1.24 U2.1(VDD) U3.8
P12V_SLOT1: C8.1 C10.1 C12.1 C34.1 J1.A2 J1.A3 J1.B1 J1.B2 J1.B3 J3.A2 J3.A3 J3.B1 J3.B2 J3.B3
P12V_SLOT2: C1.1 C3.1 C5.1 C29.1 C30.1 C31.1 C32.1 C39.1 C41.1 C43.1 J2.A2 J2.A3 J2.B1 J2.B2 J2.B3 J6.2
CLK_100M_CPU1_RISER_DN: J3.A14 U8.2
CLK_100M_CPU1_RISER_DP: J3.A13 U8.3
CLK_100M_SLOT1_DN: J1.A14 R31.2(B)
CLK_100M_SLOT1_DP: J1.A13 R30.2(B)
CLK_100M_SLOT1_R_DN: R31.1 U8.14
CLK_100M_SLOT1_R_DP: R30.1 U8.15
CLK_100M_SLOT2_DN: J2.A14 R29.2(B)
CLK_100M_SLOT2_DP: J2.A13 R28.2(B)
CLK_100M_SLOT2_R_DN: R29.1 U8.19
CLK_100M_SLOT2_R_DP: R28.1 U8.20
CPLD_PWRBRK_N: J3.B30 R88.2(B) U5.2 U7.2
GF_SLOT1_X1_PRSNT_N: J1.B17 J3.B17
GF_SLOT1_X4_PRSNT_N: J1.B31 J3.B31
GF_SLOT1_X8_PRSNT_N: J1.B48 J3.B48
GF_SLOT1_X16_PRSNT_N: J1.B81 J3.B81
I2C_BUF_CH2_SCL: R25.2(B) U1.9
I2C_BUF_CH2_SDA: R24.2(B) U1.8
I2C_BUF_CH3_SCL: R64.2(B) U1.11
I2C_BUF_CH3_SDA: R63.2(B) U1.10
I2C_BUF_CH4_SCL: R66.2(B) U1.14
I2C_BUF_CH4_SDA: R65.2(B) U1.13
I2C_BUF_CH5_SCL: R68.2(B) U1.16
I2C_BUF_CH5_SDA: R67.2(B) U1.15
I2C_BUF_CH6_SCL: R58.1 R59.1 R70.2(B) U1.18
I2C_BUF_CH6_SDA: R40.1 R41.1 R69.2(B) U1.17
I2C_BUF_CH7_SCL: R72.2(B) U1.20
I2C_BUF_CH7_SDA: R71.2(B) U1.19
I2C_BUF_SLOT1_SCL: Q4.D R23.2(B) R83.1 U1.7
I2C_BUF_SLOT1_SDA: Q2.D R22.2(B) R85.1 U1.6
I2C_BUF_SLOT2_SCL: Q3.D R21.2(B) R82.1 U1.5
I2C_BUF_SLOT2_SDA: Q1.D R20.2(B) R84.1 U1.4
I2C_EMC1413_SCL: R59.2(B) U2.10
I2C_EMC1413_SDA: R41.2(B) U2.9
I2C_FRU_SCL: R58.2(B) U3.6
I2C_FRU_SDA: R40.2(B) U3.5
I2C_MB_RISER_SCL: J3.B5 R27.2(B) R57.1
I2C_MB_RISER_SDA: J3.B6 R17.1 R26.2(B)
I2C_PCA9548_SCL: R57.2(B) U1.22
I2C_PCA9548_SDA: R17.2(B) U1.23
I2C_SLOT1_R_SCL: J1.B5 R9.2(B)
I2C_SLOT1_R_SDA: J1.B6 R10.2(B)
I2C_SLOT1_SCL: Q4.S R9.1 R39.2(B) R83.2(B)
I2C_SLOT1_SDA: Q2.S R10.1 R37.2(B) R85.2(B)
I2C_SLOT2_R_SCL: J2.B5 R1.2(B)
I2C_SLOT2_R_SDA: J2.B6 R2.2(B)
I2C_SLOT2_SCL: Q3.S R1.1 R38.2(B) R82.2(B)
I2C_SLOT2_SDA: Q1.S R2.1 R36.2(B) R84.2(B)
JTAG_R_TCK: J1.A5 R51.1
JTAG_R_TDI: J1.A6 R52.1
JTAG_R_TDO: J1.A7 R53.1
JTAG_R_TMS: J1.A8 R54.1
JTAG_TCK: J3.A5 R8.2(B) R51.2(B)
JTAG_TDI: J3.A6 R5.2(B) R52.2(B)
JTAG_TDO: J3.A7 R6.2(B) R53.2(B)
JTAG_TMS: J3.A8 R7.2(B) R54.2(B)
JTAG_TRST_N: J1.B9 J3.B9 R50.2(B)
NC_GF_A19: J3.A19
NC_GF_A32: J3.A32
NC_GF_A33: J3.A33
NC_GF_A50: J3.A50
NC_GF_B12: J3.B12
NC_GF_B82: J3.B82
NC_J1_A19: J2.A19
NC_J1_A32: J2.A32
NC_J1_A33: J2.A33
NC_J1_A50: J2.A50
NC_J1_B17: J2.B17
NC_J1_B31: J2.B31
NC_J1_B49: J2.B48
NC_J1_B81: J2.B81
NC_J1_B82: J2.B82
NC_J2_A19: J1.A19
NC_J2_A32: J1.A32
NC_J2_A33: J1.A33
NC_J2_A50: J1.A50
NC_J2_B82: J1.B82
PCA9548_ADD0: R12.1 R55.2(B) U1.1
PCA9548_ADD1: R13.2(B) R14.1 U1.2
PCA9548_ADD2: R16.1 R56.2(B) U1.21
PE_CPU1_SLOT1_RX_DN<0>: J1.A17 J3.A17
PE_CPU1_SLOT1_RX_DN<1>: J1.A22 J3.A22
PE_CPU1_SLOT1_RX_DN<2>: J1.A26 J3.A26
PE_CPU1_SLOT1_RX_DN<3>: J1.A30 J3.A30
PE_CPU1_SLOT1_RX_DN<4>: J1.A36 J3.A36
PE_CPU1_SLOT1_RX_DN<5>: J1.A40 J3.A40
PE_CPU1_SLOT1_RX_DN<6>: J1.A44 J3.A44
PE_CPU1_SLOT1_RX_DN<7>: J1.A48 J3.A48
PE_CPU1_SLOT1_RX_DN<8>: J1.A53 J3.A53
PE_CPU1_SLOT1_RX_DN<9>: J1.A57 J3.A57
PE_CPU1_SLOT1_RX_DN<10>: J1.A61 J3.A61
PE_CPU1_SLOT1_RX_DN<11>: J1.A65 J3.A65
PE_CPU1_SLOT1_RX_DN<12>: J1.A69 J3.A69
PE_CPU1_SLOT1_RX_DN<13>: J1.A73 J3.A73
PE_CPU1_SLOT1_RX_DN<14>: J1.A77 J3.A77
PE_CPU1_SLOT1_RX_DN<15>: J1.A81 J3.A81
PE_CPU1_SLOT1_RX_DP<0>: J1.A16 J3.A16
PE_CPU1_SLOT1_RX_DP<1>: J1.A21 J3.A21
PE_CPU1_SLOT1_RX_DP<2>: J1.A25 J3.A25
PE_CPU1_SLOT1_RX_DP<3>: J1.A29 J3.A29
PE_CPU1_SLOT1_RX_DP<4>: J1.A35 J3.A35
PE_CPU1_SLOT1_RX_DP<5>: J1.A39 J3.A39
PE_CPU1_SLOT1_RX_DP<6>: J1.A43 J3.A43
PE_CPU1_SLOT1_RX_DP<7>: J1.A47 J3.A47
PE_CPU1_SLOT1_RX_DP<8>: J1.A52 J3.A52
PE_CPU1_SLOT1_RX_DP<9>: J1.A56 J3.A56
PE_CPU1_SLOT1_RX_DP<10>: J1.A60 J3.A60
PE_CPU1_SLOT1_RX_DP<11>: J1.A64 J3.A64
PE_CPU1_SLOT1_RX_DP<12>: J1.A68 J3.A68
PE_CPU1_SLOT1_RX_DP<13>: J1.A72 J3.A72
PE_CPU1_SLOT1_RX_DP<14>: J1.A76 J3.A76
PE_CPU1_SLOT1_RX_DP<15>: J1.A80 J3.A80
PE_CPU1_SLOT1_TX_DN<0>: J1.B15 J3.B15
PE_CPU1_SLOT1_TX_DN<1>: J1.B20 J3.B20
PE_CPU1_SLOT1_TX_DN<2>: J1.B24 J3.B24
PE_CPU1_SLOT1_TX_DN<3>: J1.B28 J3.B28
PE_CPU1_SLOT1_TX_DN<4>: J1.B34 J3.B34
PE_CPU1_SLOT1_TX_DN<5>: J1.B38 J3.B38
PE_CPU1_SLOT1_TX_DN<6>: J1.B42 J3.B42
PE_CPU1_SLOT1_TX_DN<7>: J1.B46 J3.B46
PE_CPU1_SLOT1_TX_DN<8>: J1.B51 J3.B51
PE_CPU1_SLOT1_TX_DN<9>: J1.B55 J3.B55
PE_CPU1_SLOT1_TX_DN<10>: J1.B59 J3.B59
PE_CPU1_SLOT1_TX_DN<11>: J1.B63 J3.B63
PE_CPU1_SLOT1_TX_DN<12>: J1.B67 J3.B67
PE_CPU1_SLOT1_TX_DN<13>: J1.B71 J3.B71
PE_CPU1_SLOT1_TX_DN<14>: J1.B75 J3.B75
PE_CPU1_SLOT1_TX_DN<15>: J1.B79 J3.B79
PE_CPU1_SLOT1_TX_DP<0>: J1.B14 J3.B14
PE_CPU1_SLOT1_TX_DP<1>: J1.B19 J3.B19
PE_CPU1_SLOT1_TX_DP<2>: J1.B23 J3.B23
PE_CPU1_SLOT1_TX_DP<3>: J1.B27 J3.B27
PE_CPU1_SLOT1_TX_DP<4>: J1.B33 J3.B33
PE_CPU1_SLOT1_TX_DP<5>: J1.B37 J3.B37
PE_CPU1_SLOT1_TX_DP<6>: J1.B41 J3.B41
PE_CPU1_SLOT1_TX_DP<7>: J1.B45 J3.B45
PE_CPU1_SLOT1_TX_DP<8>: J1.B50 J3.B50
PE_CPU1_SLOT1_TX_DP<9>: J1.B54 J3.B54
PE_CPU1_SLOT1_TX_DP<10>: J1.B58 J3.B58
PE_CPU1_SLOT1_TX_DP<11>: J1.B62 J3.B62
PE_CPU1_SLOT1_TX_DP<12>: J1.B66 J3.B66
PE_CPU1_SLOT1_TX_DP<13>: J1.B70 J3.B70
PE_CPU1_SLOT1_TX_DP<14>: J1.B74 J3.B74
PE_CPU1_SLOT1_TX_DP<15>: J1.B78 J3.B78
PE_CPU1_SLOT2_RX_DN<0>: J2.A17 J4.3
PE_CPU1_SLOT2_RX_DN<1>: J2.A22 J4.6
PE_CPU1_SLOT2_RX_DN<2>: J2.A26 J4.9
PE_CPU1_SLOT2_RX_DN<3>: J2.A30 J4.12
PE_CPU1_SLOT2_RX_DN<4>: J2.A36 J4.15
PE_CPU1_SLOT2_RX_DN<5>: J2.A40 J4.18
PE_CPU1_SLOT2_RX_DN<6>: J2.A44 J4.21
PE_CPU1_SLOT2_RX_DN<7>: J2.A48 J4.24
PE_CPU1_SLOT2_RX_DN<8>: J2.A53 J5.3
PE_CPU1_SLOT2_RX_DN<9>: J2.A57 J5.6
PE_CPU1_SLOT2_RX_DN<10>: J2.A61 J5.9
PE_CPU1_SLOT2_RX_DN<11>: J2.A65 J5.12
PE_CPU1_SLOT2_RX_DN<12>: J2.A69 J5.15
PE_CPU1_SLOT2_RX_DN<13>: J2.A73 J5.18
PE_CPU1_SLOT2_RX_DN<14>: J2.A77 J5.21
PE_CPU1_SLOT2_RX_DN<15>: J2.A81 J5.24
PE_CPU1_SLOT2_RX_DP<0>: J2.A16 J4.2
PE_CPU1_SLOT2_RX_DP<1>: J2.A21 J4.5
PE_CPU1_SLOT2_RX_DP<2>: J2.A25 J4.8
PE_CPU1_SLOT2_RX_DP<3>: J2.A29 J4.11
PE_CPU1_SLOT2_RX_DP<4>: J2.A35 J4.14
PE_CPU1_SLOT2_RX_DP<5>: J2.A39 J4.17
PE_CPU1_SLOT2_RX_DP<6>: J2.A43 J4.20
PE_CPU1_SLOT2_RX_DP<7>: J2.A47 J4.23
PE_CPU1_SLOT2_RX_DP<8>: J2.A52 J5.2
PE_CPU1_SLOT2_RX_DP<9>: J2.A56 J5.5
PE_CPU1_SLOT2_RX_DP<10>: J2.A60 J5.8
PE_CPU1_SLOT2_RX_DP<11>: J2.A64 J5.11
PE_CPU1_SLOT2_RX_DP<12>: J2.A68 J5.14
PE_CPU1_SLOT2_RX_DP<13>: J2.A72 J5.17
PE_CPU1_SLOT2_RX_DP<14>: J2.A76 J5.20
PE_CPU1_SLOT2_RX_DP<15>: J2.A80 J5.23
PE_CPU1_SLOT2_TX_DN<0>: J2.B15 J4.48
PE_CPU1_SLOT2_TX_DN<1>: J2.B20 J4.45
PE_CPU1_SLOT2_TX_DN<2>: J2.B24 J4.42
PE_CPU1_SLOT2_TX_DN<3>: J2.B28 J4.39
PE_CPU1_SLOT2_TX_DN<4>: J2.B34 J4.36
PE_CPU1_SLOT2_TX_DN<5>: J2.B38 J4.33
PE_CPU1_SLOT2_TX_DN<6>: J2.B42 J4.30
PE_CPU1_SLOT2_TX_DN<7>: J2.B46 J4.27
PE_CPU1_SLOT2_TX_DN<8>: J2.B51 J5.48
PE_CPU1_SLOT2_TX_DN<9>: J2.B55 J5.45
PE_CPU1_SLOT2_TX_DN<10>: J2.B59 J5.42
PE_CPU1_SLOT2_TX_DN<11>: J2.B63 J5.39
PE_CPU1_SLOT2_TX_DN<12>: J2.B67 J5.36
PE_CPU1_SLOT2_TX_DN<13>: J2.B71 J5.33
PE_CPU1_SLOT2_TX_DN<14>: J2.B75 J5.30
PE_CPU1_SLOT2_TX_DN<15>: J2.B79 J5.27
PE_CPU1_SLOT2_TX_DP<0>: J2.B14 J4.49
PE_CPU1_SLOT2_TX_DP<1>: J2.B19 J4.46
PE_CPU1_SLOT2_TX_DP<2>: J2.B23 J4.43
PE_CPU1_SLOT2_TX_DP<3>: J2.B27 J4.40
PE_CPU1_SLOT2_TX_DP<4>: J2.B33 J4.37
PE_CPU1_SLOT2_TX_DP<5>: J2.B37 J4.34
PE_CPU1_SLOT2_TX_DP<6>: J2.B41 J4.31
PE_CPU1_SLOT2_TX_DP<7>: J2.B45 J4.28
PE_CPU1_SLOT2_TX_DP<8>: J2.B50 J5.49
PE_CPU1_SLOT2_TX_DP<9>: J2.B54 J5.46
PE_CPU1_SLOT2_TX_DP<10>: J2.B58 J5.43
PE_CPU1_SLOT2_TX_DP<11>: J2.B62 J5.40
PE_CPU1_SLOT2_TX_DP<12>: J2.B66 J5.37
PE_CPU1_SLOT2_TX_DP<13>: J2.B70 J5.34
PE_CPU1_SLOT2_TX_DP<14>: J2.B74 J5.31
PE_CPU1_SLOT2_TX_DP<15>: J2.B78 J5.28
PU_EMC1413_ADDR: R87.2(B) U2.7
PU_EMC1413_ALERT_N: R86.2(B) U2.8
RISER_WAKE_N: J3.B11 R48.2(B) R49.2(B) R61.2(B)
RST_PCA9548_N: R62.2(B) U1.3
RST_PE_N: J3.A11 U4.2 U6.2
RST_PE_SLOT1_N: J1.A11 U6.4(Y)
RST_PE_SLOT2_N: J2.A11 U4.4(Y)
SLOT1_B12_PWRBRK_N: J1.B12 R75.2(B)
SLOT1_B30_PWRBRK_N: J1.B30 R76.2(B)
SLOT1_GF_PRSNT_N: J1.A1 J3.A1
SLOT1_PWRBRK_N: R75.1 R76.1 R90.2(B) U7.4(Y)
SLOT1_WAKE_N: R11.1 R49.1
SLOT1_WAKE_R_N: J1.B11 R11.2(B)
SLOT2_B12_PWRBRK_N: J2.B12 R73.2(B)
SLOT2_B30_PWRBRK_N: J2.B30 R74.2(B)
SLOT2_JTAG_TCK: J2.A5 R81.2(B)
SLOT2_JTAG_TDI: J2.A6 R78.2(B)
SLOT2_JTAG_TDO: J2.A7 R79.2(B)
SLOT2_JTAG_TMS: J2.A8 R80.2(B)
SLOT2_JTAG_TRST_N: J2.B9 R77.2(B)
SLOT2_PRSNT_N: J2.A1 R4.1
SLOT2_PWRBRK_N: R73.1 R74.1 R89.2(B) U5.4(Y)
SLOT2_WAKE_N: R3.1 R48.1
SLOT2_WAKE_R_N: J2.B11 R3.2(B)
TEMP_SEN1_DN: C24.2(B) Q6.2(E) U2.3
TEMP_SEN1_DP: C24.1 Q6.1 Q6.3 U2.2
TEMP_SEN2_DN: C23.2(B) Q5.2(E) U2.5
TEMP_SEN2_DP: C23.1 Q5.1 Q5.3 U2.4
UNNAMED_11_9DBL411B_I133_OE0: R18.2(B) U8.1 U8.16
UNNAMED_11_9DBL411B_I133_OE2: R19.2(B) U8.6 U8.13
UNNAMED_12_2N7002_I1_G: Q1.G R32.2(B)
UNNAMED_12_2N7002_I5_G: Q3.G R34.2(B)
UNNAMED_12_2N7002_I21_G: Q2.G R33.2(B)
UNNAMED_12_2N7002_I22_G: Q4.G R35.2(B)
UNNAMED_13_AT24C64D_I41_A0: R43.1 R60.2(B) U3.1
UNNAMED_13_AT24C64D_I41_A1: R44.2(B) R45.1 U3.2
UNNAMED_13_AT24C64D_I41_A2: R46.2(B) R47.1 U3.3
UNNAMED_13_AT24C64D_I41_WP: R42.1 U3.7(WP)

Pads without a net: NOREF#4 1; NOREF#14 1; NOREF#41 1; NOREF#51 1; U4 1; U5 1; U6 1; U7 1; U8 7 8 11 12

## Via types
v1: diameter 0.508, hole 0.254, TOP to BOTTOM, 567 vias
v2: diameter 0.66, hole 0.33, TOP to BOTTOM, 7 vias

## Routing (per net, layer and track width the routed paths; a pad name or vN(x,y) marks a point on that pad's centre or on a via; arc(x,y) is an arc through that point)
GND: length 360.9
  TOP w0.254: U2.6 v1(73.9,27.7)
  TOP w0.305: J5.38 v1(60.12,59.39) ; J4.26 v1(87.27,59.26) ; J5.32 v1(56.52,59.39) ; U8.5 v1(98.43,27.29) ; J4.41 v1(96.27,59.39) ; J4.29 v1(89.07,59.33) ; v1(115.1,26.14) 114.68,25.72 U6.3 ; U4.3 v1(117.1,26.18) ; J5.47 v1(65.52,59.26) ; J5.26 v1(52.92,59.26) ; J5.35 v1(58.32,59.39) ; J4.47 v1(99.87,59.26) ; J4.35 v1(92.67,59.39) ; U5.3 v1(111.99,43.69) ; J4.32 v1(90.87,59.39) ; J5.25 v1(52.92,64.54) ; J5.29 v1(54.72,59.39) ; J4.44 v1(98.07,59.39) ; v1(101.67,59.39) J4.50 ; U8.10 v1(98.45,24.04) ; v1(67.32,59.39) J5.50 ; J4.38 v1(94.47,59.39) ; J4.25 v1(87.27,64.54) ; U8.17 v1(101.51,27.94) ; J5.44 v1(63.72,59.39) ; J5.41 v1(61.92,59.39) ; U1.12 v1(137.61,32.05)
  TOP w0.356: U7.3 v1(110.87,26.3) ; J5.19 56.52,64.59 v1(56.47,64.65) ; J4.22 v1(89.07,64.65) ; C18.2 v1(106.82,27.94) ; J5.7 63.72,64.59 v1(63.67,64.65) ; v1(101.62,64.65) 101.67,64.59 J4.1 ; J5.10 v1(61.92,64.65) ; J5.4 v1(65.52,64.65) ; J5.22 v1(54.72,64.65) ; v1(111.24,11.3) 112.07,11.3 C35.2 111.56,10.54 v1(111.24,10.54) ; v1(90.82,64.65) 90.87,64.59 J4.19 ; v1(92.77,26.92) 93.4,26.92 C15.2 93.62,26.26 v1(92.77,26.26) ; R4.2 v1(128.4,33.15) ; R8.1 v1(129.15,11.05) ; J4.4 v1(99.87,64.65) ; J5.1 67.32,64.59 v1(67.27,64.65) ; J4.16 v1(92.67,64.65) ; J4.10 v1(96.27,64.65) ; v1(60.07,64.65) 60.12,64.59 J5.13 ; J5.16 v1(58.32,64.65) ; J4.7 98.07,64.59 v1(98.02,64.65) ; J4.13 94.47,64.59 v1(94.42,64.65) ; C16.2 v1(95.37,25.98) ; R81.1 v1(120.02,31.1) ; C28.2 v1(110.37,29.34) ; C19.2 v1(95.37,22.81) ; R18.1 v1(106.82,26.92)
  TOP w0.381: R12.2 v1(129.66,40.62) ; R14.2 v1(129.68,39.6) ; C21.2 v1(68.04,31.2)
  TOP w0.406: C12.2 v1(122.32,23.72) ; C6.2 v1(116.32,43.94) ; v1(124.45,45.72) 124.45,45.05 C1.2 125.21,44.99 v1(125.21,45.72) ; C22.2 v1(133.21,42.67) ; v1(118.48,25.27) 118.48,24.7 C9.2 119.26,24.71 v1(119.26,25.27) ; C14.2 114.29,23.37 v1(114.54,23.62) ; v1(124.45,25.27) 124.45,24.73 C8.2 125.21,24.67 v1(125.21,25.27) ; v1(119.26,45.59) 119.26,45.03 C33.2 118.48,45.02 v1(118.48,45.59) ; C27.2 v1(114.8,28.7) ; C5.2 v1(120.29,31.78) ; C7.2 v1(114.42,43.97) ; C26.2 v1(116.59,29.34) ; v1(117.59,23.62) 117.34,23.36 C11.2 ; R43.2 v1(146.17,43.33) ; v1(113.4,32.64) 113.4,31.81 C2.2 112.64,31.94 v1(112.64,32.64) ; R45.2 v1(146.17,45.36) ; R42.2 v1(133.21,43.94) ; C10.2 v1(123.34,23.62) ; v1(127.08,25.27) 127.08,24.67 C34.2 126.32,24.73 v1(126.32,25.27) ; C25.2 v1(109.85,47.36) ; v1(127.24,31.91) 126.57,31.91 C32.2 126.51,31.15 v1(127.24,31.15) ; C13.2 v1(116.32,23.62) ; C3.2 v1(123.34,44.04) ; C4.2 v1(117.34,43.94) ; R16.2 v1(149.21,36.81) ; C20.2 v1(145.58,40.51) ; R47.2 v1(146.17,46.38)
  TOP w0.457: J3.A51 71.78,6.53 v1(71.24,7.06) ; J3.A31 91.78,6.6 v1(92.24,7.06) ; J3.A49 73.78,6.6 73.91,6.92 v1(74.31,7.09) ; J3.A23 99.78,6.6 v1(100.24,7.06) ; J3.A71 51.78,6.53 v1(51.24,7.06) ; v1(80.24,7.06) 80.78,6.53 J3.A42 ; v1(76.24,7.06) 76.78,6.53 J3.A46 ; v1(41.24,7.06) 40.78,6.6 J3.A82 ; J3.A45 77.78,6.6 v1(78.24,7.06) ; J3.A58 64.78,6.6 v1(65.24,7.06) ; J3.A79 43.78,6.53 v1(43.24,7.06) ; J3.A41 81.78,6.6 v1(82.24,7.06) ; v1(59.24,7.06) 59.78,6.53 J3.A63 ; J3.A55 67.78,6.53 v1(67.24,7.06) ; v1(49.24,7.06) 48.78,6.6 J3.A74 ; J3.A66 56.78,6.6 v1(57.24,7.06) ; v1(84.24,7.06) 84.78,6.53 J3.A38 ; v1(96.24,7.06) 95.78,6.6 J3.A27 ; v1(107.24,7.06) 107.78,6.53 J3.A15 ; J3.A62 60.78,6.6 v1(61.24,7.06) ; J3.A59 63.78,6.53 v1(63.24,7.06) ; v1(86.24,7.06) 85.78,6.6 J3.A37 ; J3.A20 102.78,6.53 v1(102.24,7.06) ; J3.A34 88.78,6.53 v1(88.24,7.06) ; v1(94.24,7.06) 94.78,6.53 J3.A28 ; J3.A78 44.78,6.6 v1(45.24,7.06) ; v1(53.24,7.06) 52.78,6.6 J3.A70 ; J3.A24 98.78,6.53 v1(98.24,7.06) ; v1(55.24,7.06) 55.78,6.53 J3.A67 ; J3.A18 104.78,6.6 v1(105.24,7.06) ; J3.A12 110.78,6 110.57,6.21 v1(110.57,7.74) ; J3.A75 47.78,6.53 v1(47.24,7.06) ; J3.A54 68.78,6.6 v1(69.24,7.06)
  TOP w0.508: U3.4 v1(143.3,46.54) ; v1(72.25,75.62) v1(77.33,75.62) v1(82.41,75.62) ; J3.A4 v1(120.78,7.04)
  BOTTOM w0.406: J3.B13 109.78,6.12 109.29,6.61 v1(109.29,7.69)
  BOTTOM w0.457: v1(57.24,7.06) 57.78,6.53 J3.B65 ; J3.B26 96.78,6.53 v1(96.24,7.06) ; J3.B22 100.78,6.53 v1(100.24,7.06) ; v1(78.24,7.06) 78.78,6.53 J3.B44 ; v1(80.24,7.06) 79.78,6.6 J3.B43 ; J3.B32 90.78,6.79 v1(90.48,7.08) ; J3.B80 42.78,6.6 v1(43.24,7.06) ; v1(76.24,7.06) 75.78,6.6 J3.B47 ; J3.B35 87.78,6.6 v1(88.24,7.06) ; v1(65.24,7.06) 65.78,6.53 J3.B57 ; J3.B52 70.78,6.6 v1(71.24,7.06) ; v1(94.24,7.06) 93.78,6.6 J3.B29 ; J3.B72 50.78,6.6 v1(51.24,7.06) ; v1(86.24,7.06) 86.78,6.53 J3.B36 ; v1(102.24,7.06) 101.78,6.6 J3.B21 ; J3.B39 83.78,6.6 v1(84.24,7.06) ; J3.B64 58.78,6.6 v1(59.24,7.06) ; J3.B76 46.78,6.6 v1(47.24,7.06) ; J3.B40 82.78,6.53 v1(82.24,7.06) ; v1(45.24,7.06) 45.78,6.53 J3.B77 ; J3.B73 49.78,6.53 v1(49.24,7.06) ; v1(104.19,7.11) 104.19,6.31 104.78,5.73 J3.A18 ; v1(53.24,7.06) 53.78,6.53 J3.B69 ; J3.B60 62.78,6.6 v1(63.24,7.06) ; v1(55.24,7.06) 54.78,6.6 J3.B68 ; J3.B53 69.78,6.53 v1(69.24,7.06) ; v1(98.24,7.06) 97.78,6.6 J3.B25 ; J3.B56 66.78,6.6 v1(67.24,7.06) ; J3.A49 73.78,5.94 73.05,6.67 v1(73.05,7.1) ; v1(107.24,7.06) 106.78,6.6 J3.B16 ; v1(61.24,7.06) 61.78,6.53 J3.B61
  BOTTOM w0.508: J3.A4 v1(120.78,7.04) ; v1(119.1,7.04) 117.78,5.72 J3.B7
  vias: v1(0.76,73.74) v1(0.76,68.66) v1(0.76,63.58) v1(0.76,58.5) v1(0.76,53.42) v1(0.76,48.34) v1(0.76,43.26) v1(0.76,38.18) v1(0.76,33.1) v1(0.76,28.02) v1(0.76,22.94) v1(0.76,17.86) v1(0.76,12.78) v1(2.1,75.63) v1(2.1,10.81) v1(7.18,75.63) v1(11.04,10.77) v1(12.26,75.63) v1(12.26,10.81) v1(17.34,75.63) v1(17.34,10.81) v1(22.42,75.63) v1(22.42,10.81) v1(25.01,60.71) v1(25.01,59.69) v1(25.01,58.8) v1(25.01,57.78) v1(25.01,56.9) v1(25.01,55.88) v1(25.01,54.99) v1(25.01,53.98) v1(25.01,53.09) v1(25.01,52.07) v1(25.9,61.72) v1(27.5,75.63) v1(27.5,10.81) v1(32.58,75.63) v1(32.58,10.81) v1(37.66,75.63) v1(37.66,10.81) v1(37.96,62.48) v1(37.96,61.59) v1(37.96,60.58) v1(37.96,59.69) v1(37.96,58.67) v1(37.96,57.78) v1(37.96,56.77) v1(37.96,55.88) v1(37.96,54.86) v1(37.96,53.85) v1(37.96,52.83) v1(37.96,51.82) v1(42.74,75.63) v1(42.8,42.29) v1(44.55,42.29) v1(46.8,42.29) v1(48.55,42.29) v1(50.8,42.29) v1(52.55,42.29) v1(52.96,66.12) v1(54.71,66.12) v1(54.93,42.29) v1(56.57,66.12) v1(56.67,42.29) v1(58.31,66.12) v1(58.93,42.29) v1(60.17,66.12) v1(60.67,42.29) v1(61.92,66.12) v1(62.93,42.29) v1(63.78,66.12) v1(64.67,42.29) v1(65.53,66.12) v1(66.8,42.29) v1(68.55,42.29) v1(70.8,42.29) v1(72.55,42.29) v1(72.89,43.81) v1(76.83,42.29) v1(78.58,42.29) v1(80.83,42.29) v1(82.58,42.29) v1(84.83,42.29) v1(86.58,42.29) v1(87.31,66.12) v1(88.83,42.29) v1(89.06,66.12) v1(90.58,42.29) v1(90.92,66.12) v1(92.66,66.12) v1(93.38,21.89) v1(94.4,21.89) v1(94.52,66.12) v1(94.83,42.29) v1(96.27,66.12) v1(96.58,42.29) v1(98.13,66.12) v1(98.83,42.29) v1(99.88,66.12) v1(100.58,42.29) v1(102.83,42.29) v1(104.58,42.29) v1(106.8,42.29) v1(108.55,42.29) v1(113.86,75.63) v1(118.94,75.63) v1(119.62,51.49) v1(121.4,28.91) v1(123.66,50.09) v1(124.02,75.63) v1(126.72,9.19) v1(129.1,75.63) v1(129.1,9.18) v1(131.26,38.38) v1(131.64,33.66) v1(131.79,36.12) v1(132.02,47.27) v1(134.18,75.63) v1(134.18,9.18) v1(135.29,45.67) v1(139.26,75.63) v1(139.26,9.18) v1(143.93,34.04) v1(144.34,75.63) v1(144.34,9.18) v1(146.52,38.56) v1(149.23,73.74) v1(149.23,68.66) v1(149.23,63.58) v1(149.23,58.5) v1(149.23,53.42) v1(149.23,48.34) v1(149.23,43.26) v1(149.23,38.18) v1(149.23,33.1) v1(149.23,28.02) v1(149.23,22.94) v1(149.23,17.86) v1(149.23,12.78)
P3V3_CLK_BUF_VDDA: length 1.9
  TOP w0.305: U8.4 95.85,27.94 C16.1
  vias: v1(91.99,28.55)
P3V3_CLK_BUF_VDDIO: length 3.5
  TOP w0.305: U8.18 104.73,28.59 C18.1
  TOP w0.406: C18.1 105.18,27.74 v1(104.76,27.74)
  vias: v1(91.53,26.34) v1(91.96,25.78) v2(94.17,29.97)
P3V3_SLOT1: length 8
  TOP w0.356: R19.1 v1(106.92,23.88) ; U7.5 109.57,28.67 C28.1 v1(108.95,28.67) ; R39.1 123.31,24.54 v1(123.58,24.26) ; C27.1 113.38,28.7 U6.5 ; R50.1 v1(113.27,23.62)
  TOP w0.406: v1(113.38,29.34) C27.1 ; v1(121.27,24.26) R37.1 R35.1 ; R33.1 v1(120.26,24.26)
  vias: v1(91.48,21.87) v1(92.37,21.87) v1(116.32,21.46) v1(116.32,9.53) v1(116.3,8.4) v1(116.31,7.35) v1(116.83,9.02) v1(116.83,7.87) v1(117.34,21.46) v1(117.34,9.53) v1(117.34,8.38) v1(117.34,7.37) v1(118.1,21.46) v1(118.99,21.46) v2(107.96,26.49)
P3V3_SLOT2: length 9
  TOP w0.305: U5.5 110.69,46.45 C25.1
  TOP w0.356: U4.5 115.8,28.7 C26.1 ; v1(120.64,46.23) 120.37,46.5 R34.1 ; R32.1 v1(116.19,46.86) ; R38.1 v1(123.56,46.86) ; v1(118.83,46.2) 118.59,46.45 R36.1
  TOP w0.406: 115.51,30.3 115.79,30.02 C26.1 ; v1(109.87,46.56) C25.1
  BOTTOM w0.381: R89.1 109.57,46.26 v1(109.87,46.56)
  vias: v1(33.64,62.48) v1(33.64,61.59) v1(33.64,60.58) v1(33.64,59.69) v1(33.64,58.67) v1(33.64,57.78) v1(33.64,56.77) v1(33.64,55.88) v1(33.64,54.86) v1(33.64,53.85) v1(33.64,52.83) v1(33.64,51.82)
P3V3_STBY: length 99.1
  TOP w0.254: 69.43,29.9 69.46,29.9 69.65,29.7 U2.1
  TOP w0.305: C20.1 143.53,39.85 142.87,39.2 U1.24
  TOP w0.356: R61.1 111.55,24.33 v1(113.3,24.33) ; R79.1 v1(117.34,30.48) ; R22.1 v1(133.97,35.56) ; R78.1 v1(118.35,30.48) ; R23.1 v1(133.97,34.54) ; R80.1 v1(116.32,30.48)
  TOP w0.381: R86.1 78.96,27.81 78.98,27.79 v1(79.03,27.79) ; 69.43,29.9 C21.1 v1(68.84,31.18) ; R87.1 v1(79.03,26.67)
  TOP w0.406: C7.1 114.24,42.35 v1(114.24,41.92) ; v1(146.27,35.48) 145.96,35.79 R71.1 R72.1 ; C14.1 114.78,22.21 v1(115.05,22.48) ; R5.1 v1(129.15,12.06) ; R20.1 R21.1 v1(134.1,36.58) ; R24.1 R25.1 v1(131.81,32.51) ; R44.1 v1(146.19,44.35) ; R63.1 R64.1 v1(131.81,30.48) ; v1(148.12,39.5) R26.1 R27.1 ; R56.1 v1(148.12,35.1) ; R60.1 v1(146.17,42.31) ; R6.1 119.73,11.58 120.16,11.15 v1(120.16,11.07) ; v1(146.19,31.73) R67.1 R68.1 ; R77.1 v1(113.4,43.94) ; v1(146.32,33.76) R69.1 R70.1 ; v1(115.3,11.25) 115.63,11.58 R7.1 ; R62.1 132.56,38.56 131.99,38.56 v1(131.97,38.58) ; R66.1 R65.1 v1(146.29,29.72) ; R46.1 v1(146.19,47.39) ; R55.1 v1(131.97,40.62) ; v1(144.78,40.51) C20.1 ; R13.1 v1(131.92,39.6)
  TOP w0.457: U3.8 135.43,42.73 135.37,42.67 C22.1 v1(134.63,41.93)
  IN1 w0.508: v1(68.84,31.18) 77.95,31.18 79.03,30.1 v1(79.03,27.79) v1(79.03,26.67) 83.76,26.67 88.46,31.37 115.69,31.37 116.32,30.73 v1(116.32,30.48)
  BOTTOM w0.508: v1(114.76,7.57) 114.76,6.14 114.78,6.13 J3.B10
  vias: v1(114.75,9.47) v1(114.77,8.56) v2(115.46,44.81) v2(139.87,44.48)
P12V_SLOT1:
  vias: v1(121.91,10.67) v1(121.91,9.65) v1(121.91,8.64) v1(121.91,7.62) v1(122.31,21.11) v1(122.42,10.16) v1(122.42,9.14) v1(122.92,10.67) v1(122.92,9.65) v1(122.92,8.64) v1(122.92,7.62) v1(123.33,21.11) v1(123.43,10.16) v1(123.43,9.14) v1(123.94,10.67) v1(123.94,9.65) v1(123.94,8.64) v1(124.45,21.08) v1(125.21,21.08) v1(126.32,21.08) v1(127.08,21.08) v1(127.08,18.48) v1(127.85,18.48)
P12V_SLOT2:
  vias: v1(28.06,61.72) v1(29.07,60.71) v1(29.07,59.69) v1(29.07,58.8) v1(29.07,57.78) v1(29.07,56.9) v1(29.07,55.88) v1(29.07,54.99) v1(29.07,53.98) v1(29.07,53.09) v1(29.07,52.07) v1(121.91,32.51) v1(123.31,41.78) v1(123.69,32.64) v1(124.45,41.66) v1(124.58,32.64) v1(125.21,41.66)
CLK_100M_CPU1_RISER_DN: length 52.1
  TOP w0.127: J3.A14 108.78,5.66 109.13,6.02 109.13,6.5 105.26,10.36 104.86,10.36 103.62,11.6 103.62,13.54 104.64,14.55 104.64,17.91 105.61,18.88 105.61,20.07 105.02,20.66 90.93,20.66 89.36,22.24 89.36,28.54 90.57,29.76 94.98,29.76 95.67,29.06 96.01,29.06 96.18,29.24 U8.2
CLK_100M_CPU1_RISER_DP: length 52.1
  TOP w0.127: U8.3 96.18,28.59 96.01,28.77 95.55,28.77 94.86,29.46 90.69,29.46 89.65,28.42 89.65,26.31 89.85,26.1 89.85,25.67 89.65,25.47 89.65,25.04 89.85,24.83 89.85,24.4 89.65,24.2 89.65,23.77 89.85,23.56 89.85,23.13 89.65,22.93 89.65,22.36 91.05,20.95 105.14,20.95 105.91,20.19 105.91,18.76 104.93,17.79 104.93,14.43 103.91,13.42 103.91,11.72 104.98,10.66 105.39,10.66 109.42,6.62 109.42,6.01 109.78,5.65 J3.A13
CLK_100M_SLOT1_DN: length 15.1
  TOP w0.127: R31.2 107.02,25.22 107.47,25.22 107.68,25.01 107.68,21.48 108.54,20.62 108.9,20.62 109.64,19.88 109.64,19.04 108.57,17.98 108.57,14.52 109.11,13.99 109.11,13.99 109.12,13.98 109.19,13.77 J1.A14
CLK_100M_SLOT1_DP: length 15
  TOP w0.127: J1.A13 109.44,14.27 109.23,14.28 108.87,14.64 108.87,17.86 109.93,18.92 109.93,20 109.02,20.92 108.66,20.92 107.98,21.6 107.98,25.13 107.6,25.51 107.08,25.51 R30.2
CLK_100M_SLOT1_R_DN: length 3.5
  TOP w0.127: U8.14 103.96,25.99 104.64,25.31 105.47,25.31 R31.1
CLK_100M_SLOT1_R_DP: length 3.6
  TOP w0.127: U8.15 103.52,26.64 103.88,26.28 104.09,26.28 104.76,25.6 105.58,25.6 R30.1
CLK_100M_SLOT2_DN: length 7.7
  TOP w0.127: J2.A14 109.17,34.04 109.07,34.2 108.46,34.2 107.94,33.68 107.94,29.97 107.51,29.54 107.02,29.54 R29.2
CLK_100M_SLOT2_DP: length 7.8
  TOP w0.127: R28.2 107.08,29.83 107.39,29.83 107.65,30.09 107.65,33.8 108.34,34.49 109.23,34.49 109.46,34.63 J2.A13
CLK_100M_SLOT2_R_DN: length 3.3
  TOP w0.127: U8.19 103.6,29.24 103.8,29.44 104.41,29.44 104.54,29.57 105.53,29.57 R29.1
CLK_100M_SLOT2_R_DP: length 3.3
  TOP w0.127: U8.20 103.65,29.89 103.81,29.73 104.29,29.73 104.42,29.86 105.53,29.86 R28.1
CPLD_PWRBRK_N: length 59.9
  TOP w0.117: v1(111.06,41.88) 111.34,42.17 U5.2 ; U7.2 v1(110.22,24.43)
  BOTTOM w0.117: v1(111.06,41.88) 111.57,41.38 111.57,38.35 110.3,37.08 110.3,35.99 110.63,35.66 110.63,34.77 111.88,33.53 111.88,31.6 R88.2 112.51,30.1 111.76,29.35 111.76,27.95 112.1,27.61 112.1,26.77 110.22,24.89 v1(110.22,24.43) 110.22,23.67 106.87,20.32 94.48,20.32 93.71,19.56 93.71,19.05 92.7,18.03 92.7,14.48 91.99,13.77 91.99,11.89 91.73,11.63 91.73,6.52 92.15,6.09 92.54,6.09 92.78,5.85 J3.B30
GF_SLOT1_X1_PRSNT_N: length 15.6
  BOTTOM w0.117: J1.B17 104.8,16.47 104.8,14.26 105.78,13.28 105.78,8.9 104.76,7.88 104.76,6.85 105.78,5.83 J3.B17
GF_SLOT1_X4_PRSNT_N: length 15
  BOTTOM w0.117: J1.B31 90.74,16.41 90.74,14.27 91.68,13.34 91.68,12.06 91.4,11.79 91.4,6.37 91.78,6 J3.B31
GF_SLOT1_X8_PRSNT_N: length 16.6
  BOTTOM w0.117: J1.B48 74.77,19.43 74.77,14.96 74.46,14.21 74.07,13.63 73.72,12.8 73.72,6.91 74.78,5.86 J3.B48
GF_SLOT1_X16_PRSNT_N: length 15.2
  BOTTOM w0.117: J3.B81 41.78,5.8 40.73,6.85 40.73,8.48 v1(40.98,8.74) 41.77,9.53 41.77,13.31 40.7,14.38 40.7,15.52 41.78,16.59 J1.B81
I2C_BUF_CH2_SCL: length 3.5
  TOP w0.117: U1.9 135.51,34 134.38,32.87 v1(134.1,32.87) 133.74,32.51 R25.2
I2C_BUF_CH2_SDA: length 3.4
  TOP w0.117: U1.8 135.48,34.65 v1(135.04,34.21) 134.35,33.53 R24.2
I2C_BUF_CH3_SCL: length 4.9
  TOP w0.117: U1.11 135.58,32.7 135.24,32.37 135.24,30.99 134.46,30.2 v1(134.05,30.2) 133.77,30.48 R64.2
I2C_BUF_CH3_SDA: length 4.4
  TOP w0.117: R63.2 134.74,31.5 v1(134.77,31.53) 134.79,31.55 134.79,32.69 135.45,33.35 U1.10
I2C_BUF_CH4_SCL: length 4.3
  TOP w0.117: U1.14 142.7,32.7 143.42,31.98 v1(143.42,30.86) 143.55,30.73 R66.2
I2C_BUF_CH4_SDA: length 4.7
  TOP w0.117: R65.2 v1(144.11,29.72) 143.63,29.72 142.91,30.43 142.91,31.95 142.81,32.05 U1.13
I2C_BUF_CH5_SCL: length 3.4
  TOP w0.117: U1.16 142.95,34 143.32,33.63 v1(143.35,33.63) 143.42,33.63 144.31,32.74 R68.2
I2C_BUF_CH5_SDA: length 3.6
  TOP w0.117: U1.15 142.86,33.35 v1(143.9,32.31) 144.49,31.73 R67.2
I2C_BUF_CH6_SCL: length 110.1
  TOP w0.117: R70.2 144.25,35.3 v1(143.65,35.3) U1.18 ; R59.1 78.51,29.97 78.87,30.33 78.87,31.14 77.59,32.42 77.59,33.73 76.57,34.75 76.57,36.02 76.19,36.4 75.2,36.4 74.61,36.98 74.61,38.13 73.6,39.14 73.6,44.32 v1(73.39,44.53) ; R58.1 v1(132.96,45.21)
  BOTTOM w0.117: v1(143.65,35.3) 142.69,35.3 142.43,35.56 139.59,35.56 132.58,42.57 132.58,44.83 v1(132.96,45.21) 134.1,46.35 134.1,49.66 129.92,53.84 82.33,53.84 73.39,44.91 v1(73.39,44.53)
I2C_BUF_CH6_SDA: length 109.9
  TOP w0.117: U1.17 143.14,34.65 v1(143.24,34.54) 144.18,34.54 144.78,33.95 R69.2 ; R41.1 78.78,28.96 79.24,29.41 79.24,31.29 77.99,32.54 77.99,33.9 76.97,34.91 76.97,36.18 76.36,36.8 75.37,36.8 74.99,37.18 74.99,38.28 73.97,39.31 73.97,44.36 v1(74.16,44.55) ; R40.1 v1(132.96,46.48)
  BOTTOM w0.117: v1(143.24,34.54) 139.89,34.54 131.94,42.49 131.94,45.47 v1(132.96,46.48) 132.96,49.53 129.02,53.47 82.54,53.47 74.16,45.09 v1(74.16,44.55)
I2C_BUF_CH7_SCL: length 3
  TOP w0.117: U1.20 v1(144.03,36.6) 144.57,36.6 R72.2
I2C_BUF_CH7_SDA: length 3
  TOP w0.117: U1.19 v1(143.12,35.95) 144.61,35.95 R71.2
I2C_BUF_SLOT1_SCL: length 19.1
  TOP w0.117: R83.1 v1(131.81,34.54) R23.2 133.07,34.04 134.1,34.04 135.37,35.3 U1.7 ; Q4.D v1(122.08,29.42)
  BOTTOM w0.117: v1(131.81,34.54) 131.56,34.54 128.8,31.78 128.8,31.78 128.48,31.47 128.48,31.46 128.25,31.23 128.25,30.71 127.87,30.33 127.67,30.13 127.65,30.13 127.63,30.11 122.77,30.11 v1(122.08,29.42)
I2C_BUF_SLOT1_SDA: length 20.9
  TOP w0.117: R85.1 131.66,35.56 v1(131.79,35.43) 131.92,35.56 R22.2 133.07,35.05 134.1,35.05 135,35.95 U1.6 ; Q2.D v1(120.72,29.42)
  BOTTOM w0.117: v1(131.79,35.43) 127.88,31.52 127.88,30.86 127.5,30.48 121.78,30.48 v1(120.72,29.42)
I2C_BUF_SLOT2_SCL: length 28.1
  TOP w0.117: Q3.D v1(122.84,50.63) ; R82.1 131.53,36.58 v1(131.76,36.8) 131.99,36.58 R21.2 133.07,36.07 134.23,36.07 134.76,36.6 U1.5
  BOTTOM w0.117: v1(131.76,36.8) 129.76,36.8 128.18,38.38 128.18,49.46 126.97,50.67 v2(124.45,50.67) 124.41,50.63 v1(122.84,50.63)
I2C_BUF_SLOT2_SDA: length 31.6
  TOP w0.117: Q1.D v1(119.58,50.63) ; R84.1 v1(131.81,37.59) R20.2 133.01,38.05 133.72,38.05 134.52,37.25 U1.4
  BOTTOM w0.117: v1(131.81,37.59) 129.86,37.59 128.55,38.9 128.55,49.62 126.61,51.56 121.57,51.56 v2(120.64,50.63) v1(119.58,50.63)
